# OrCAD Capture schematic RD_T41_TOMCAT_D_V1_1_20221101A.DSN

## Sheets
1 PAGE01_COVER: title: RD_T41_TOMCAT_D; rev: 1.1; note: COVER SHEET
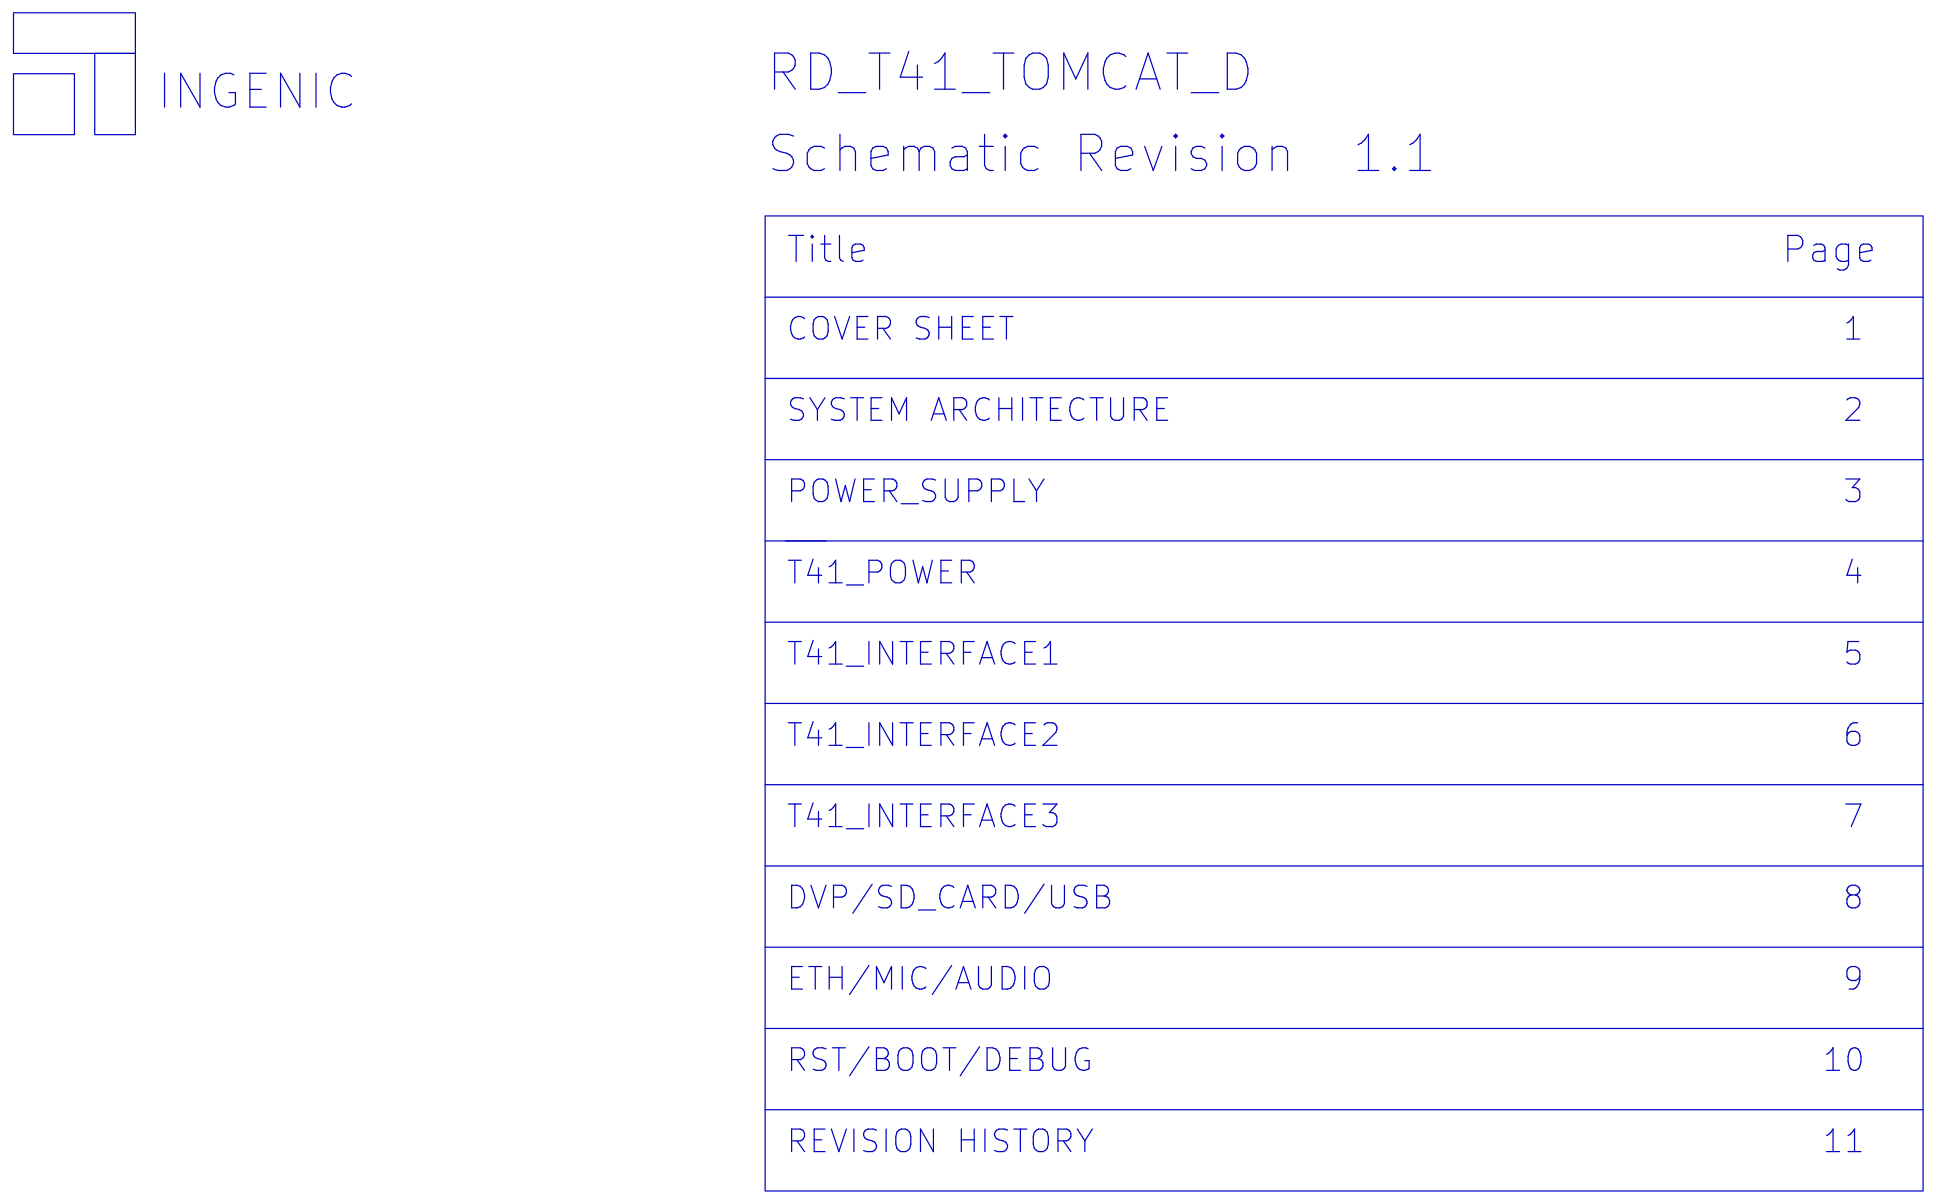
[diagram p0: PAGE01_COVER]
2 PAGE02_SYSTEM_ARCHITECT: note: SYSTEM ARCHITECTURE
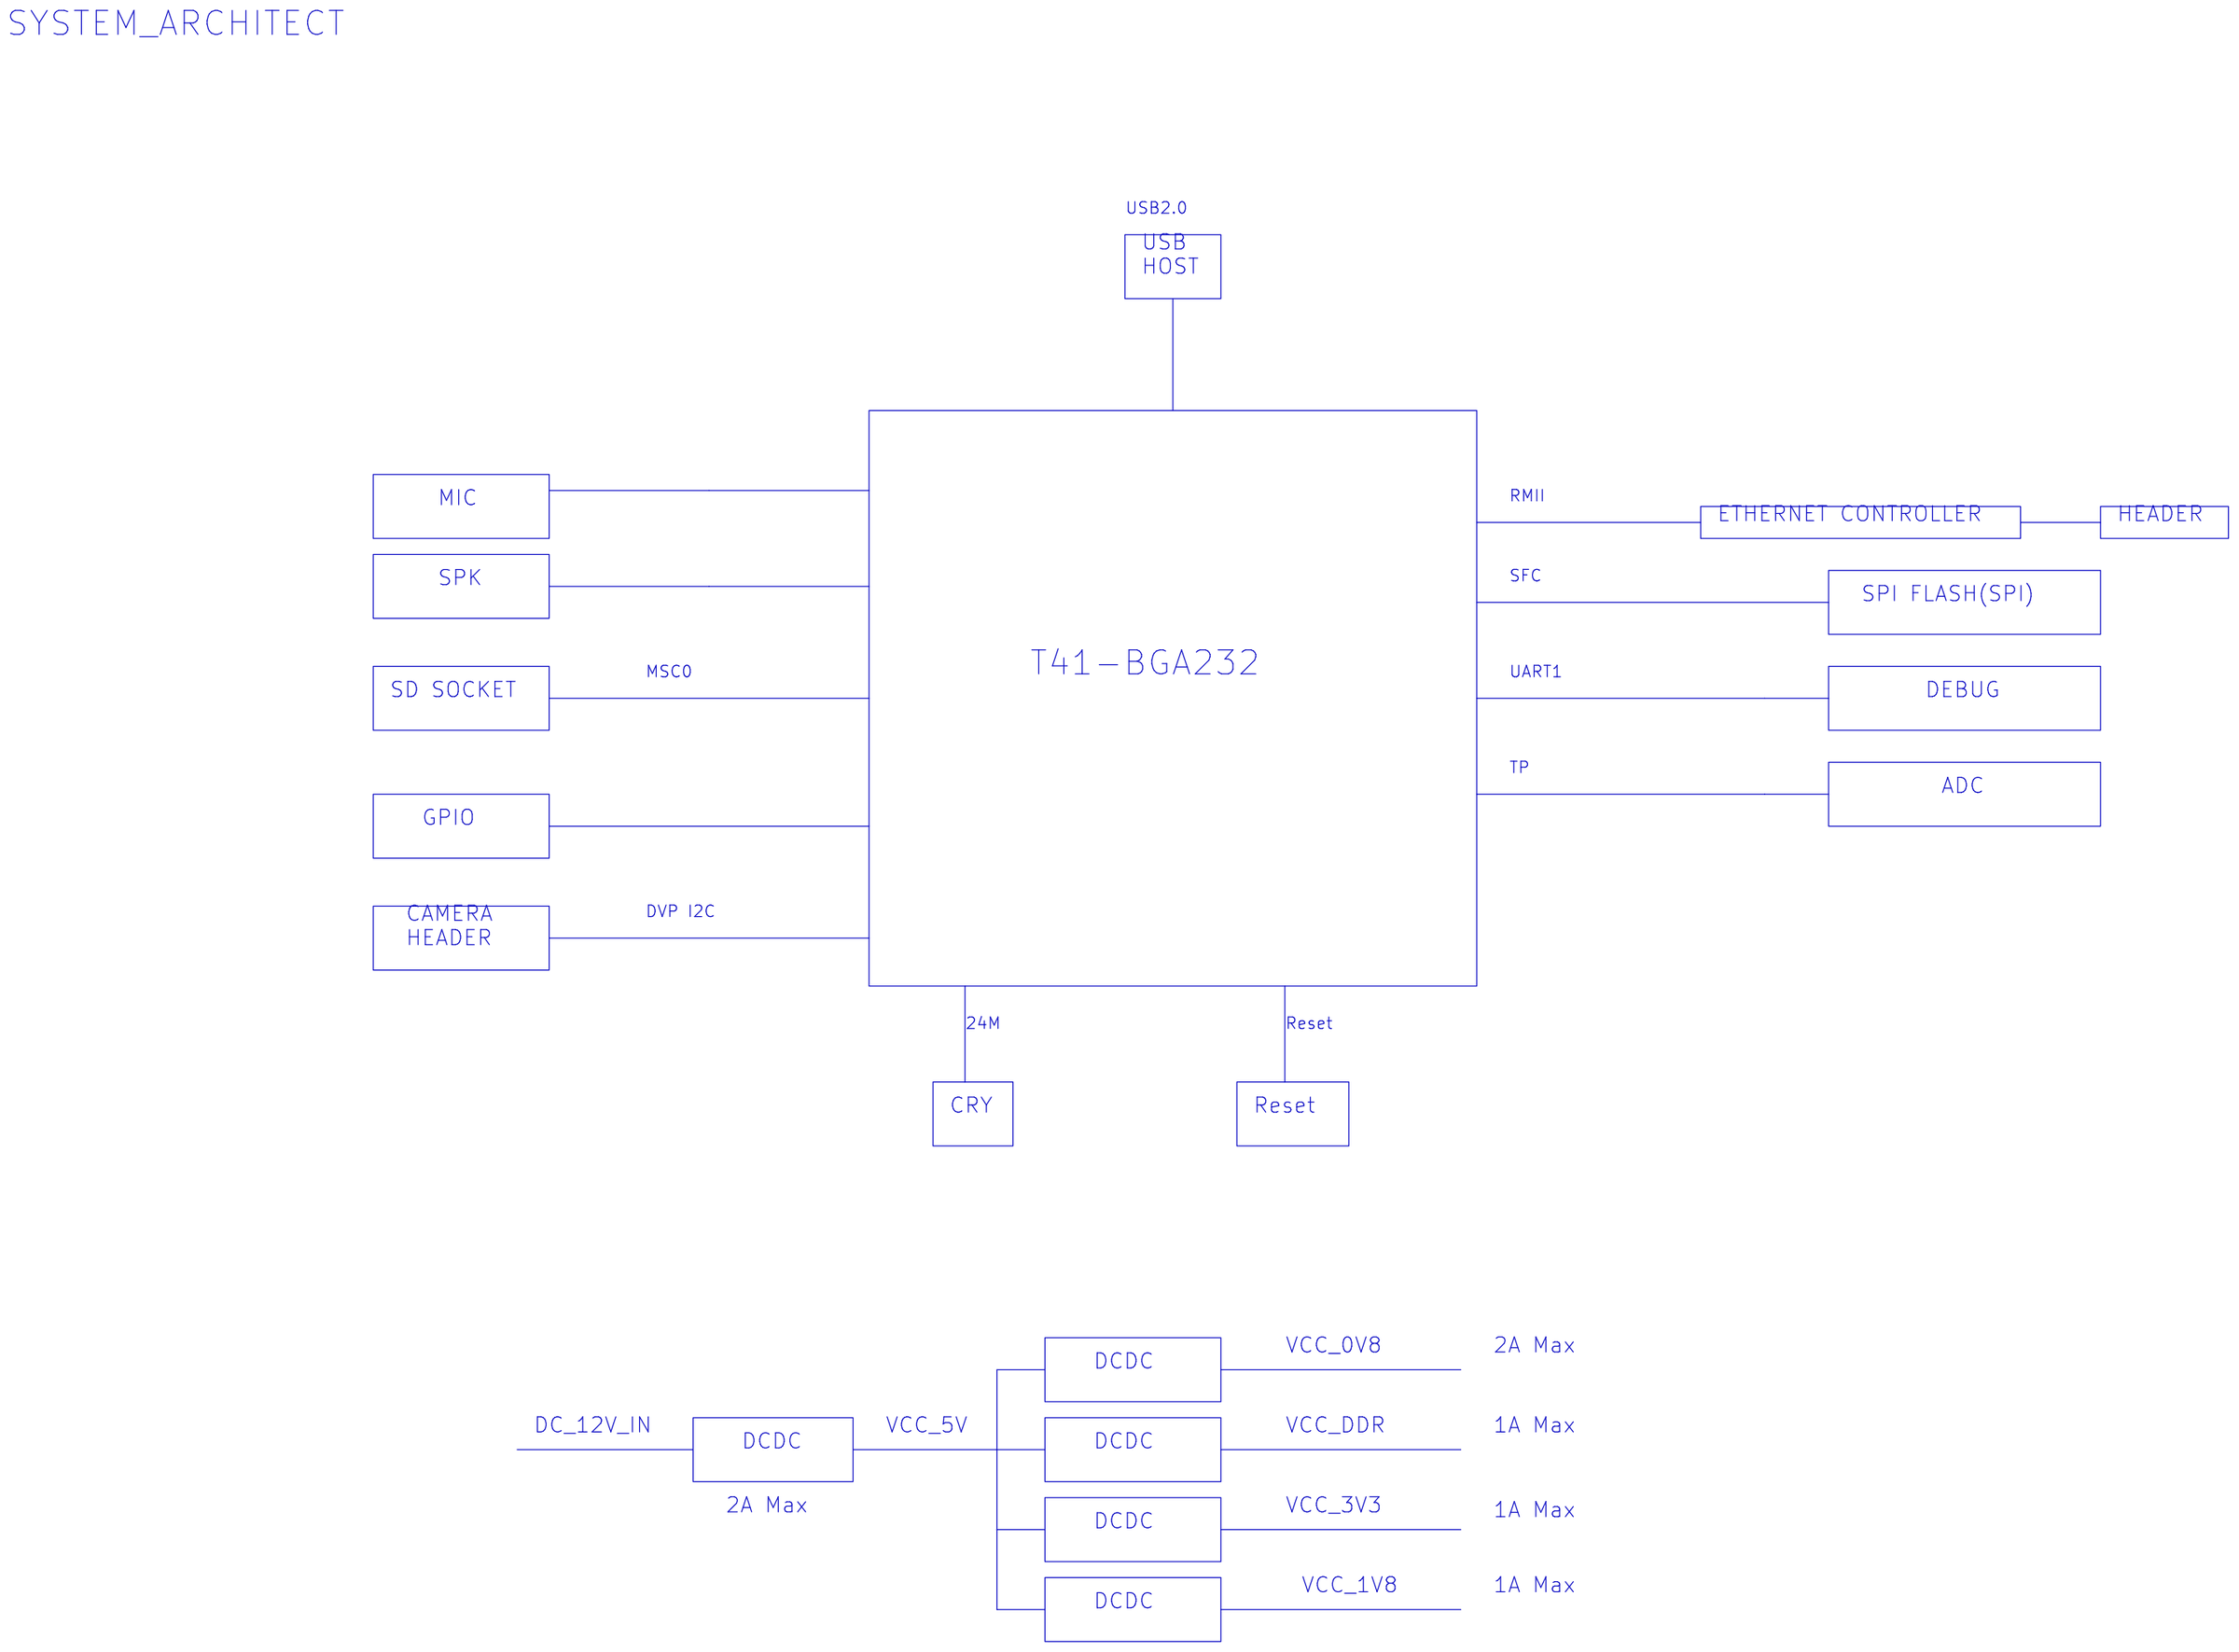
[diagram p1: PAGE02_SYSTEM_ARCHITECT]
3 PAGE03_POWER_SUPPLY: size A3; note: POWER_SUPPLY
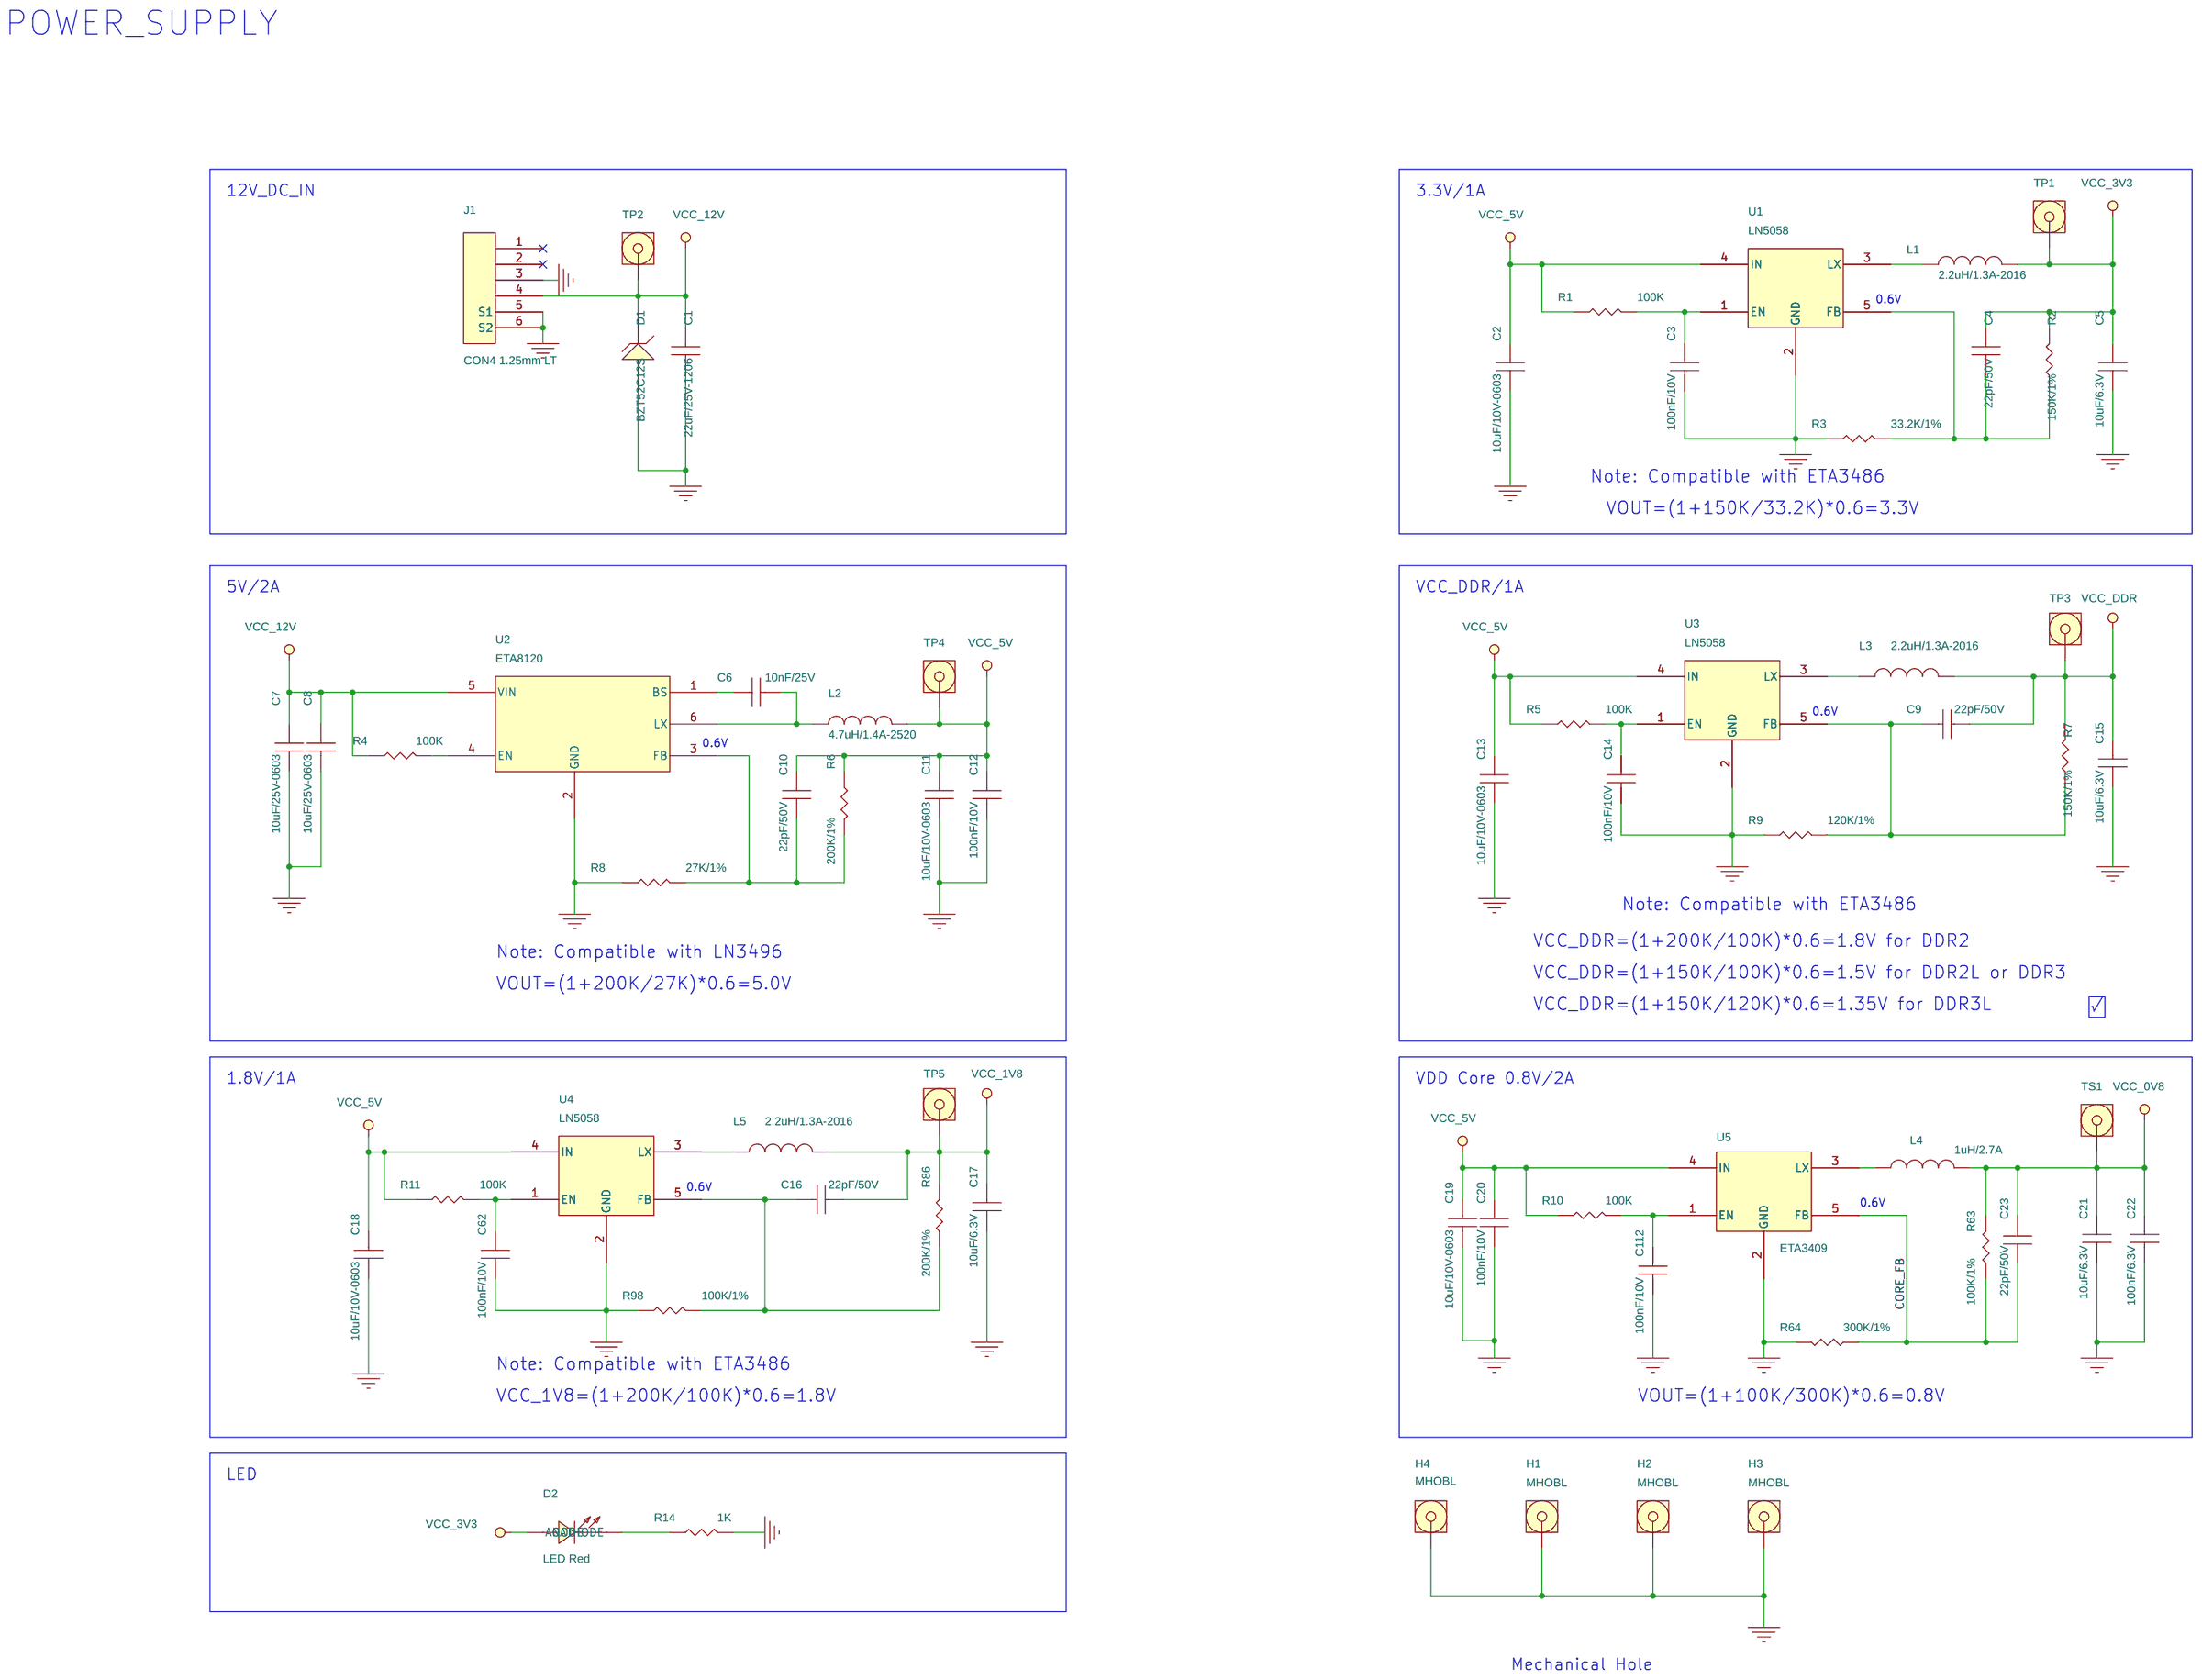
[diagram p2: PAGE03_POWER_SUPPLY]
4 PAGE04_T41_POWER: size A3; note: T41_POWER
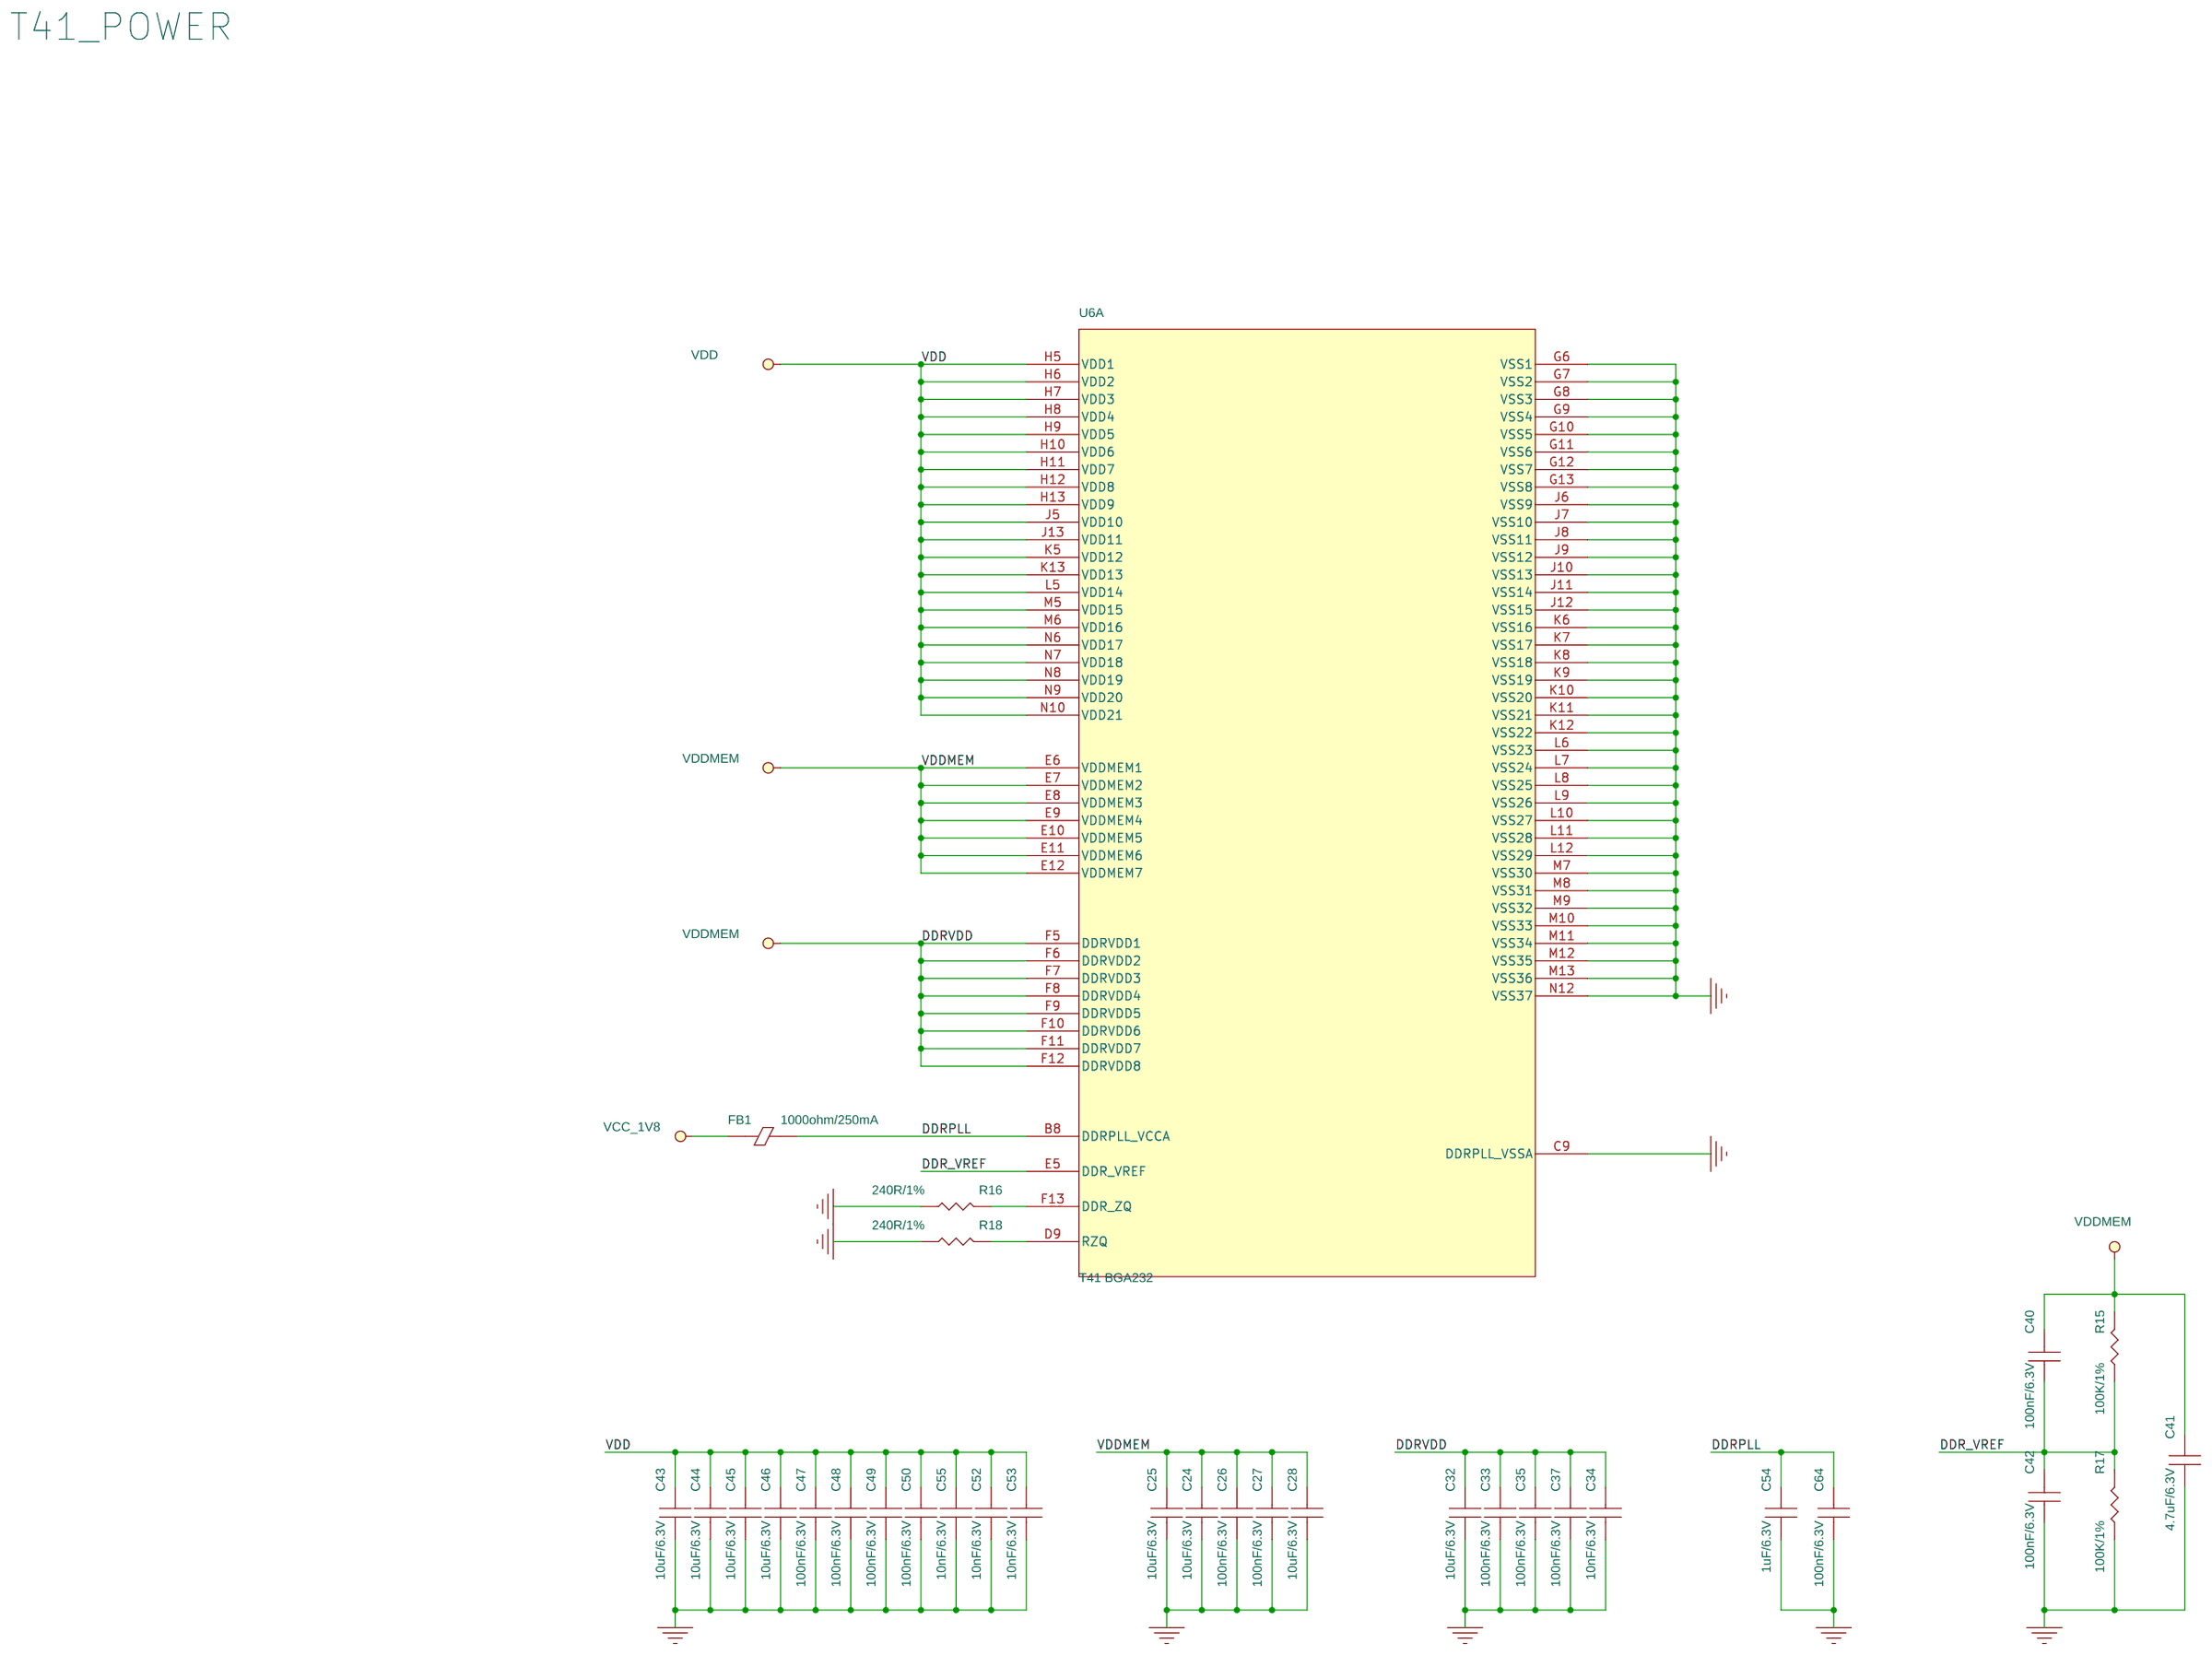
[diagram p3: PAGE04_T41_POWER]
5 PAGE05_T41_INTERFACE1: size A3; note: T41_INTERFACE1
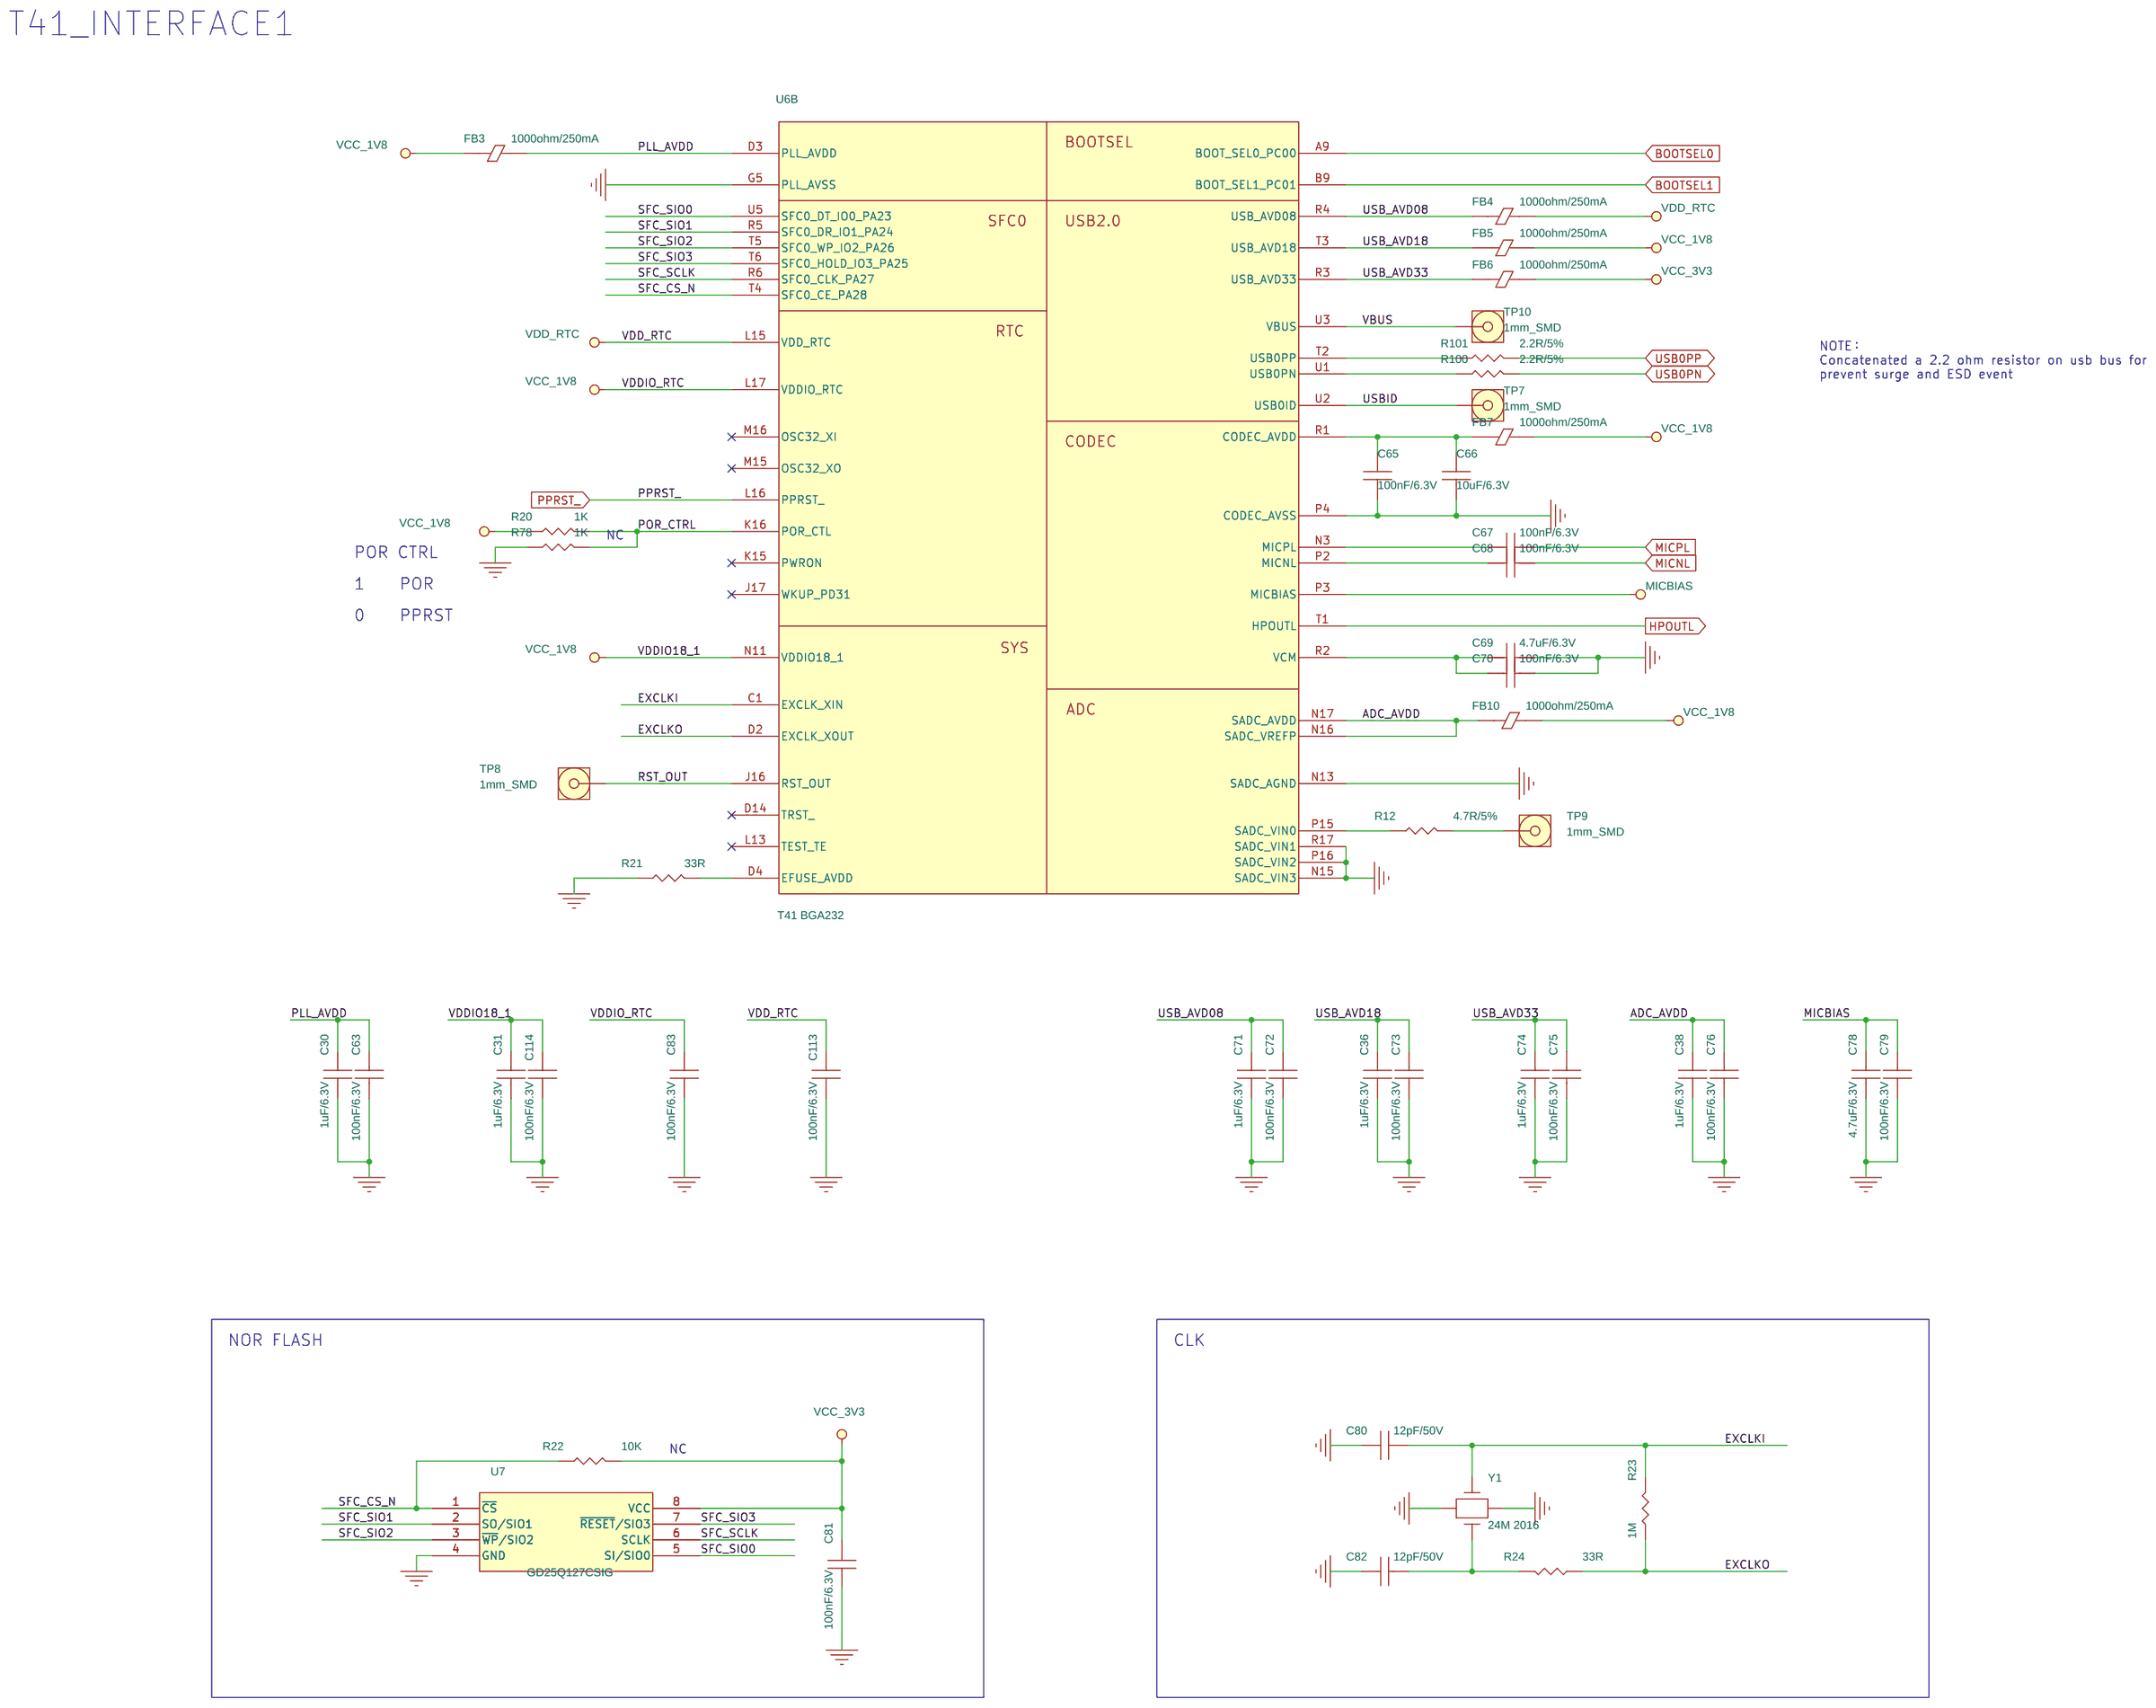
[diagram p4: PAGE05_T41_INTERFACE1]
6 PAGE06_T41_INTERFACE2: size A3; note: T41_INTERFACE2
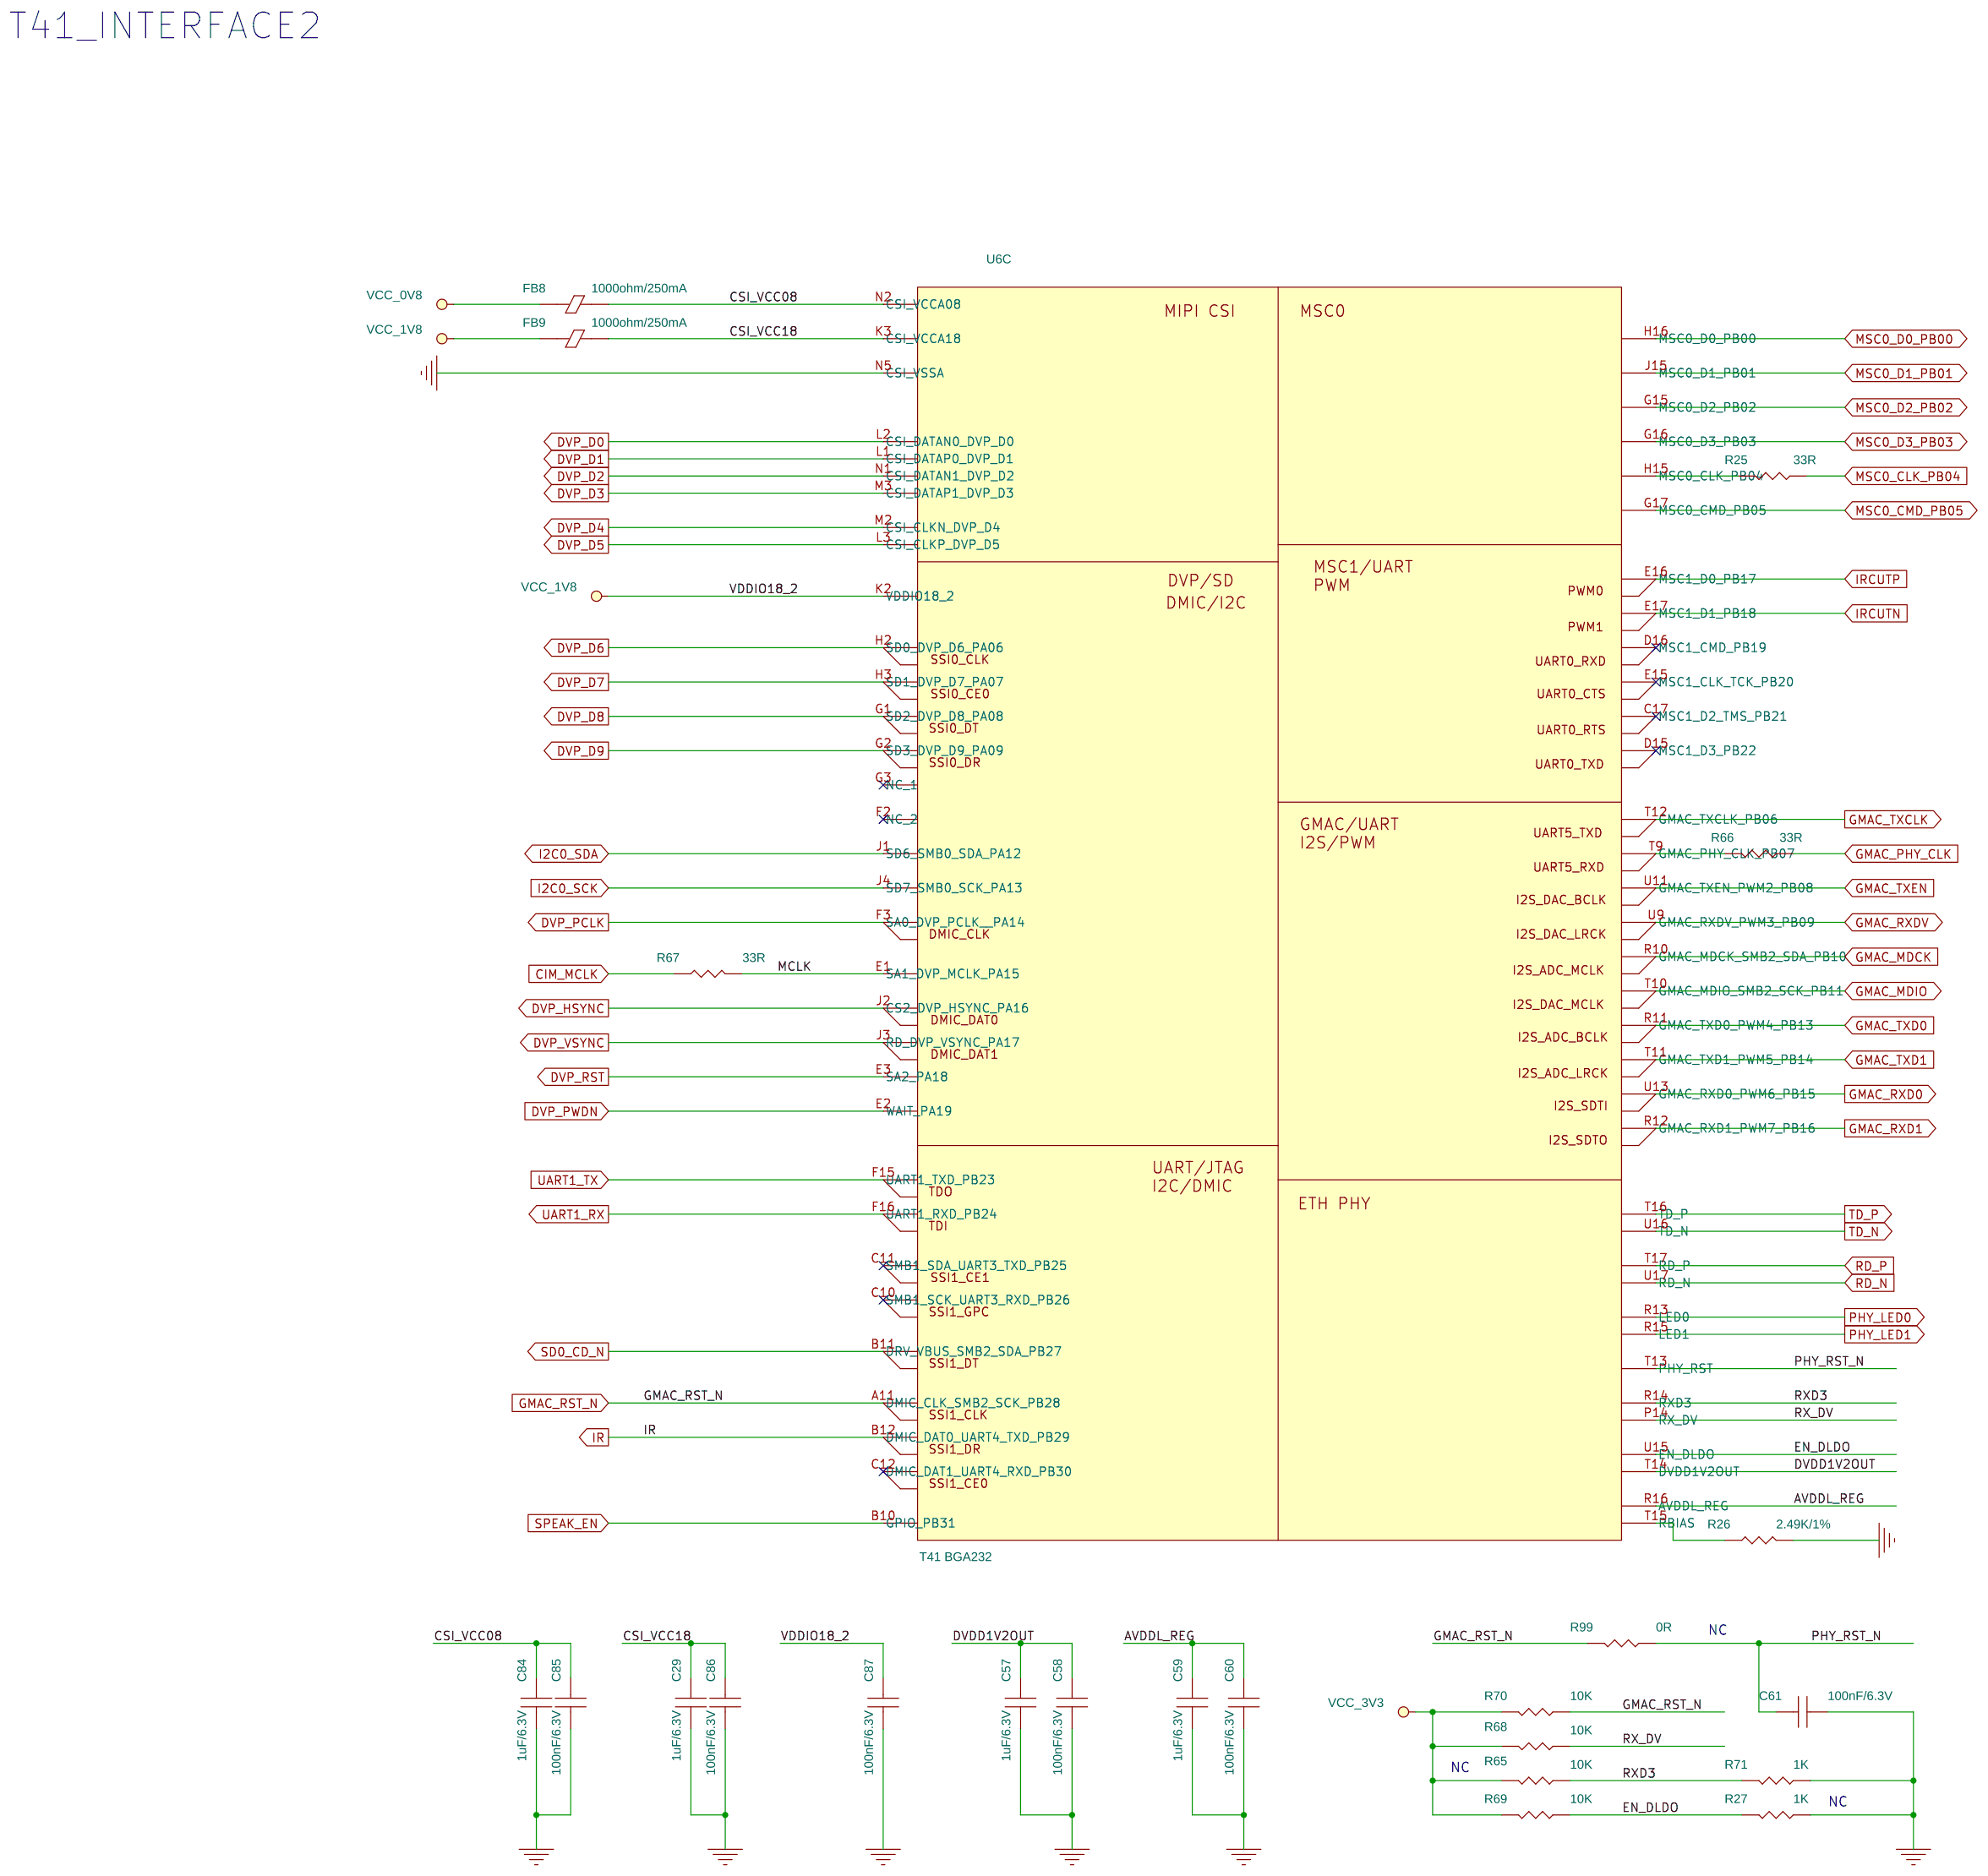
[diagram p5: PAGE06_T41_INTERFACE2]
7 PAGE07_T41_INTERFACE3: size A3; note: T41_INTERFACE3
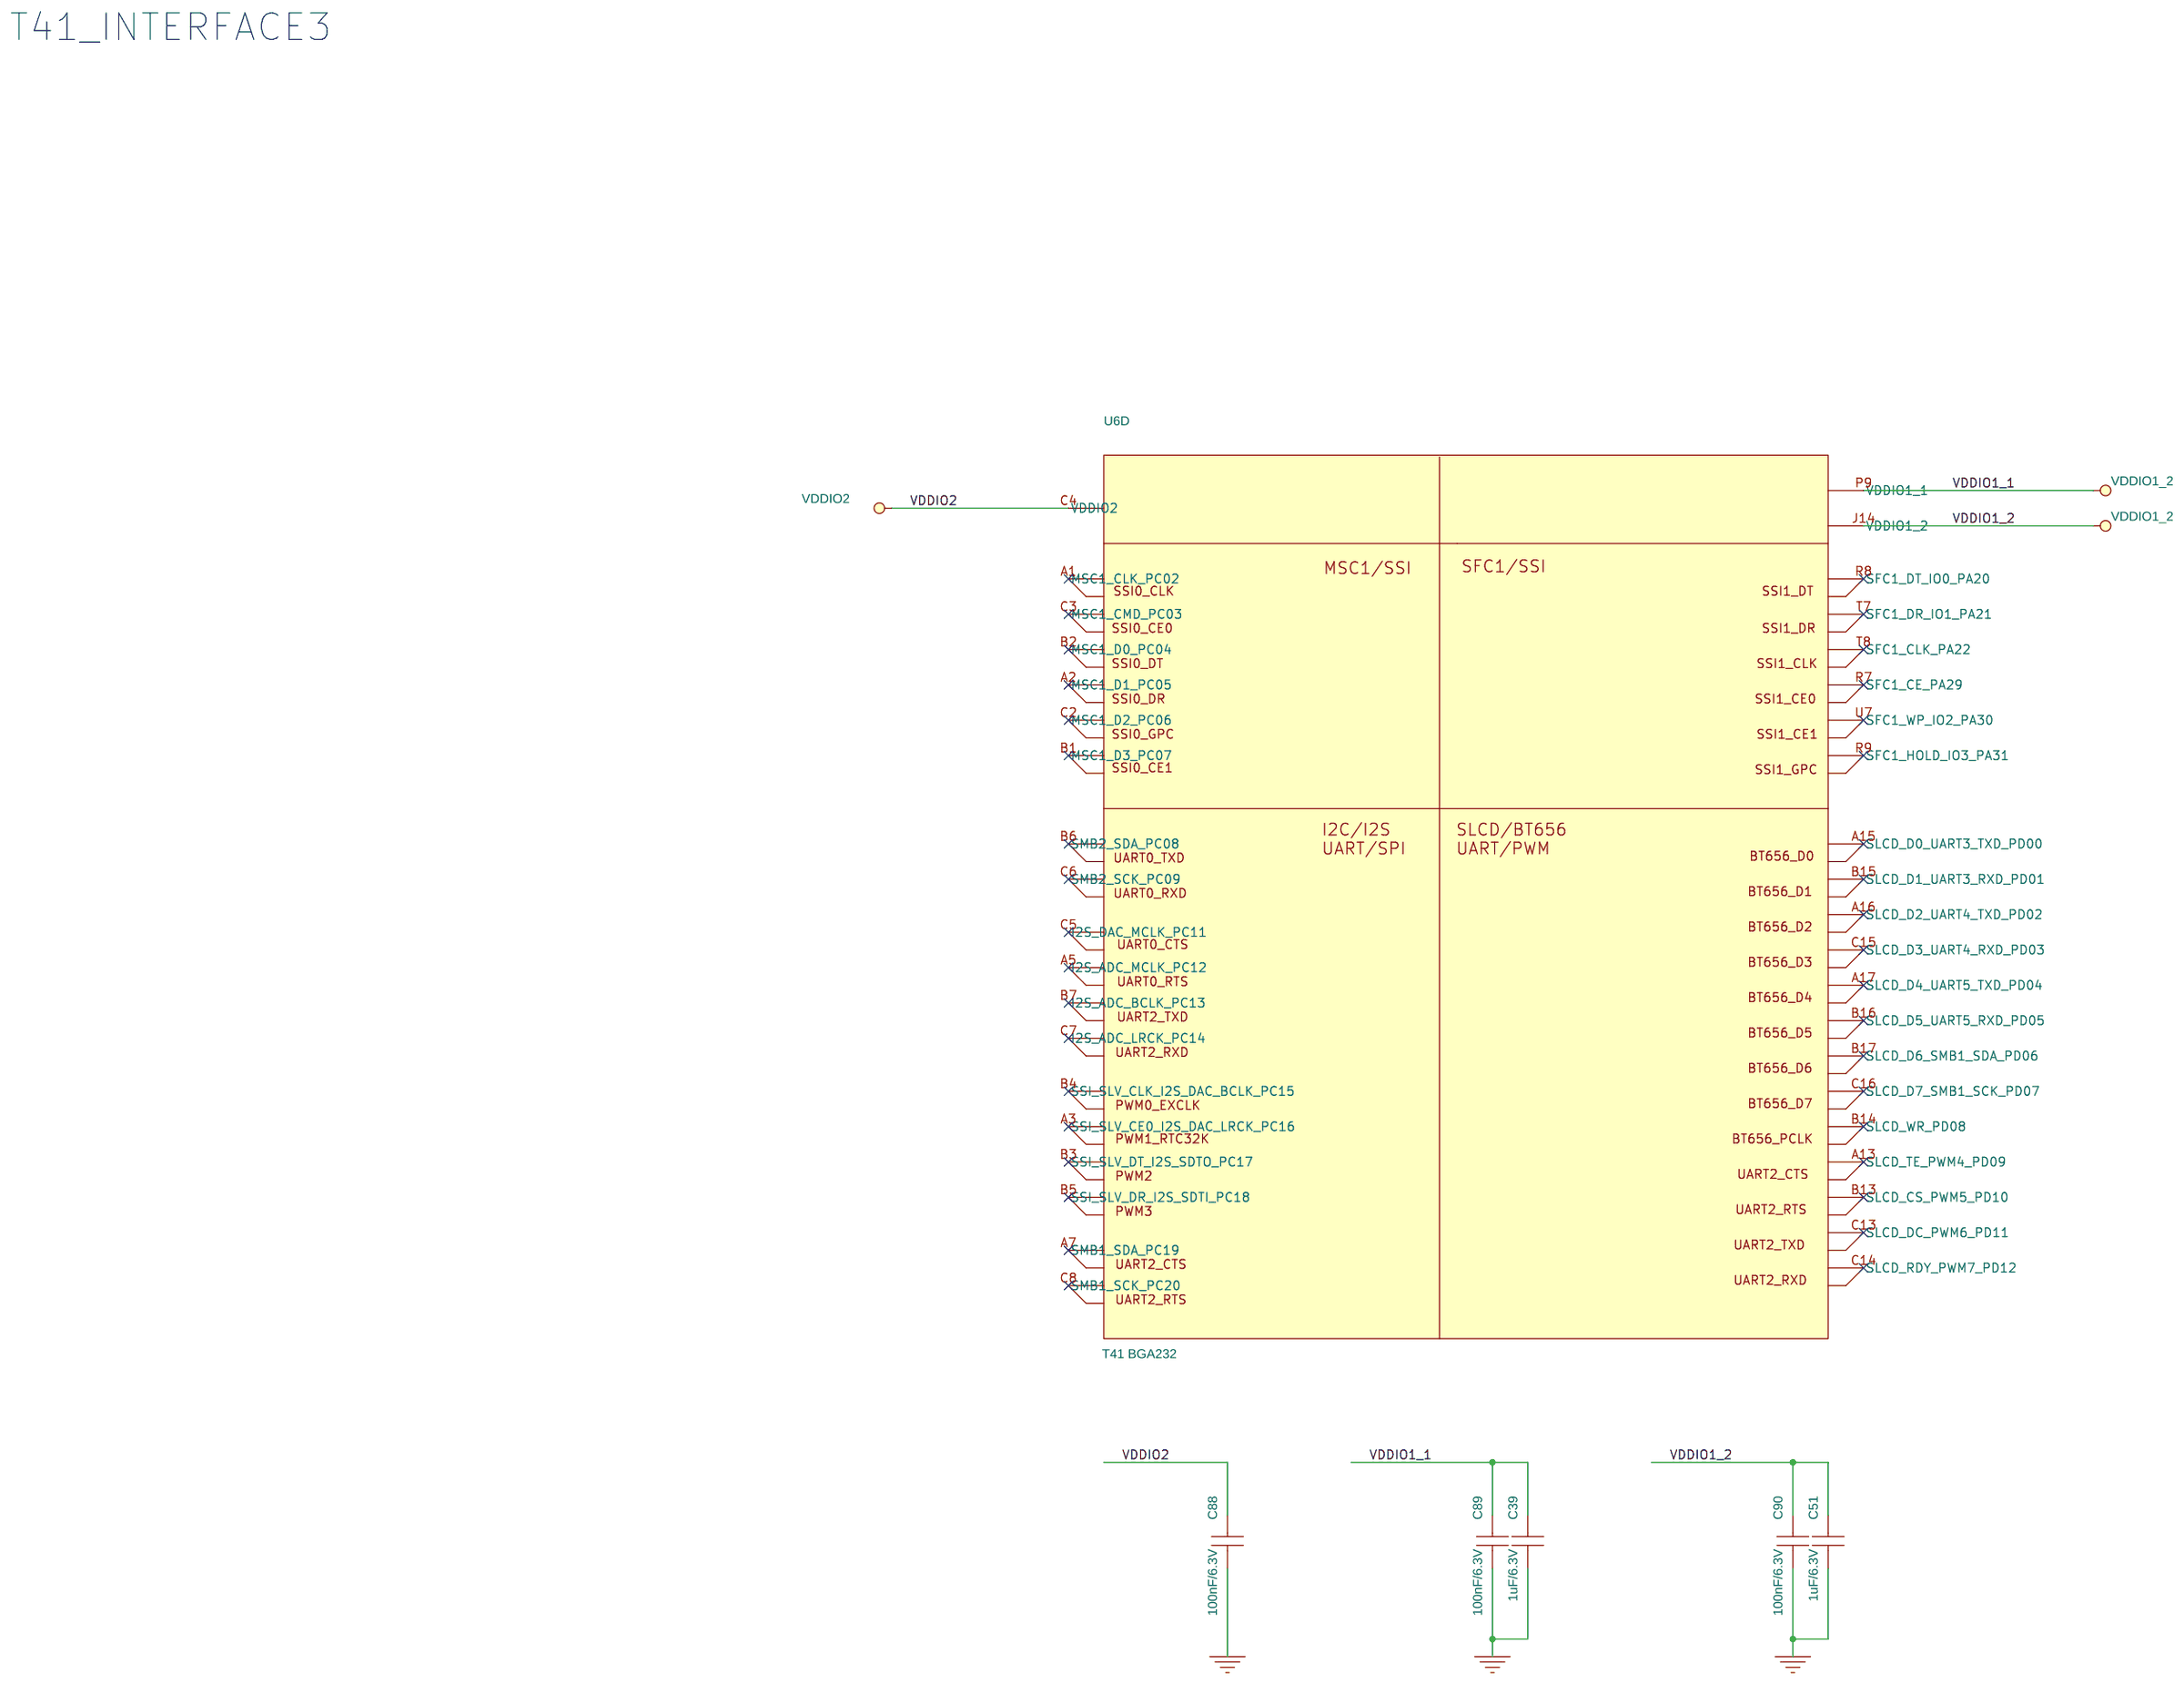
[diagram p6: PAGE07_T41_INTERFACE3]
8 PAGE11_REVISION HISTORY: note: REVISION HISTORY
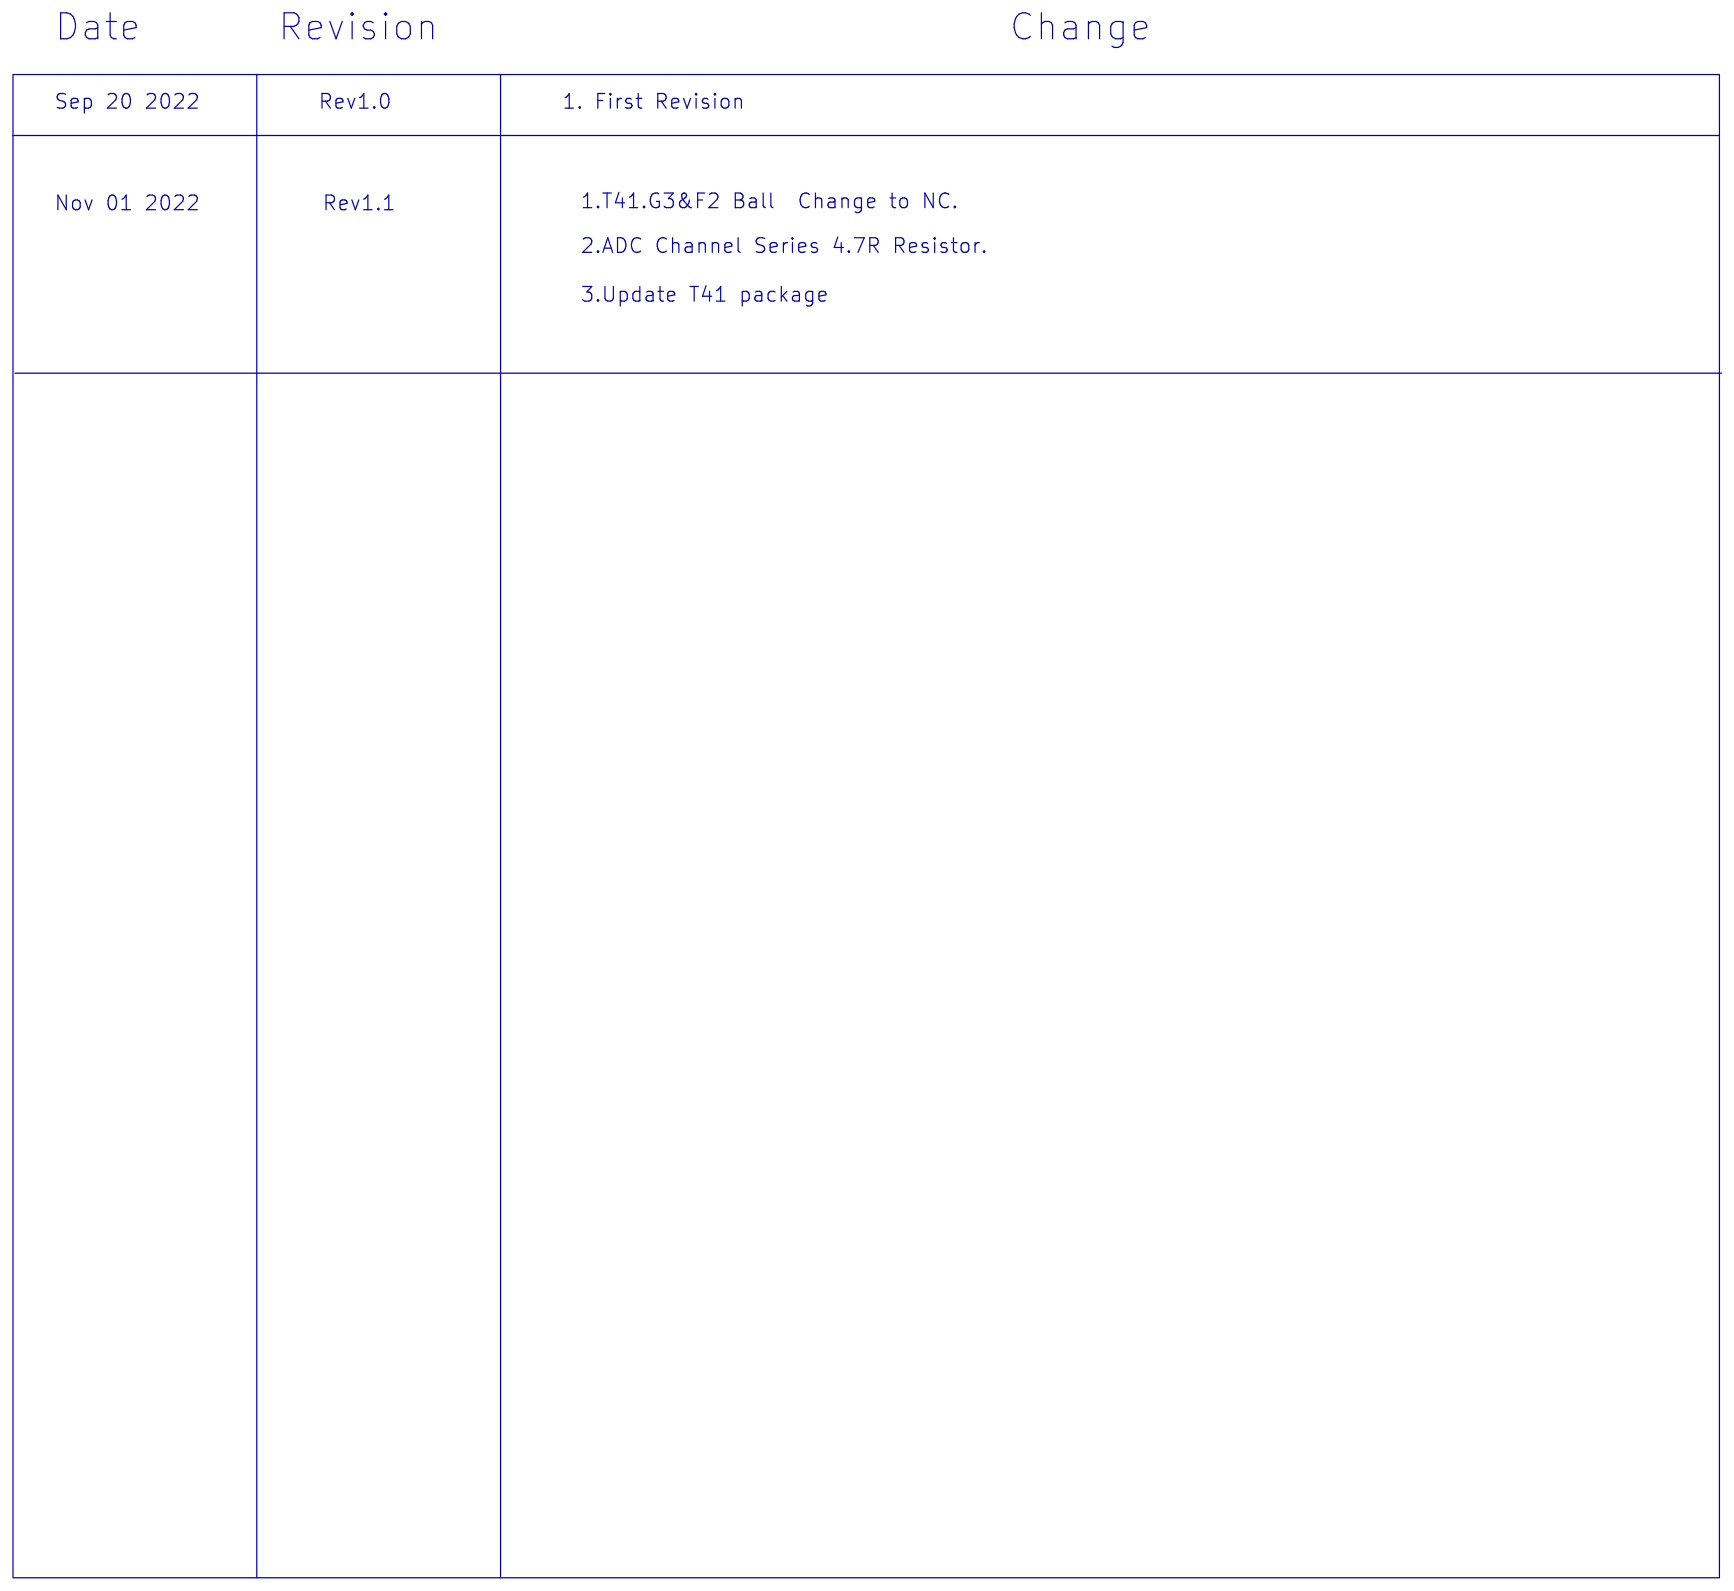
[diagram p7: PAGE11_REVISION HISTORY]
9 PAGE09_ETH/MIC/AUDIO: size A3; note: ETH/MIC/AUDIO
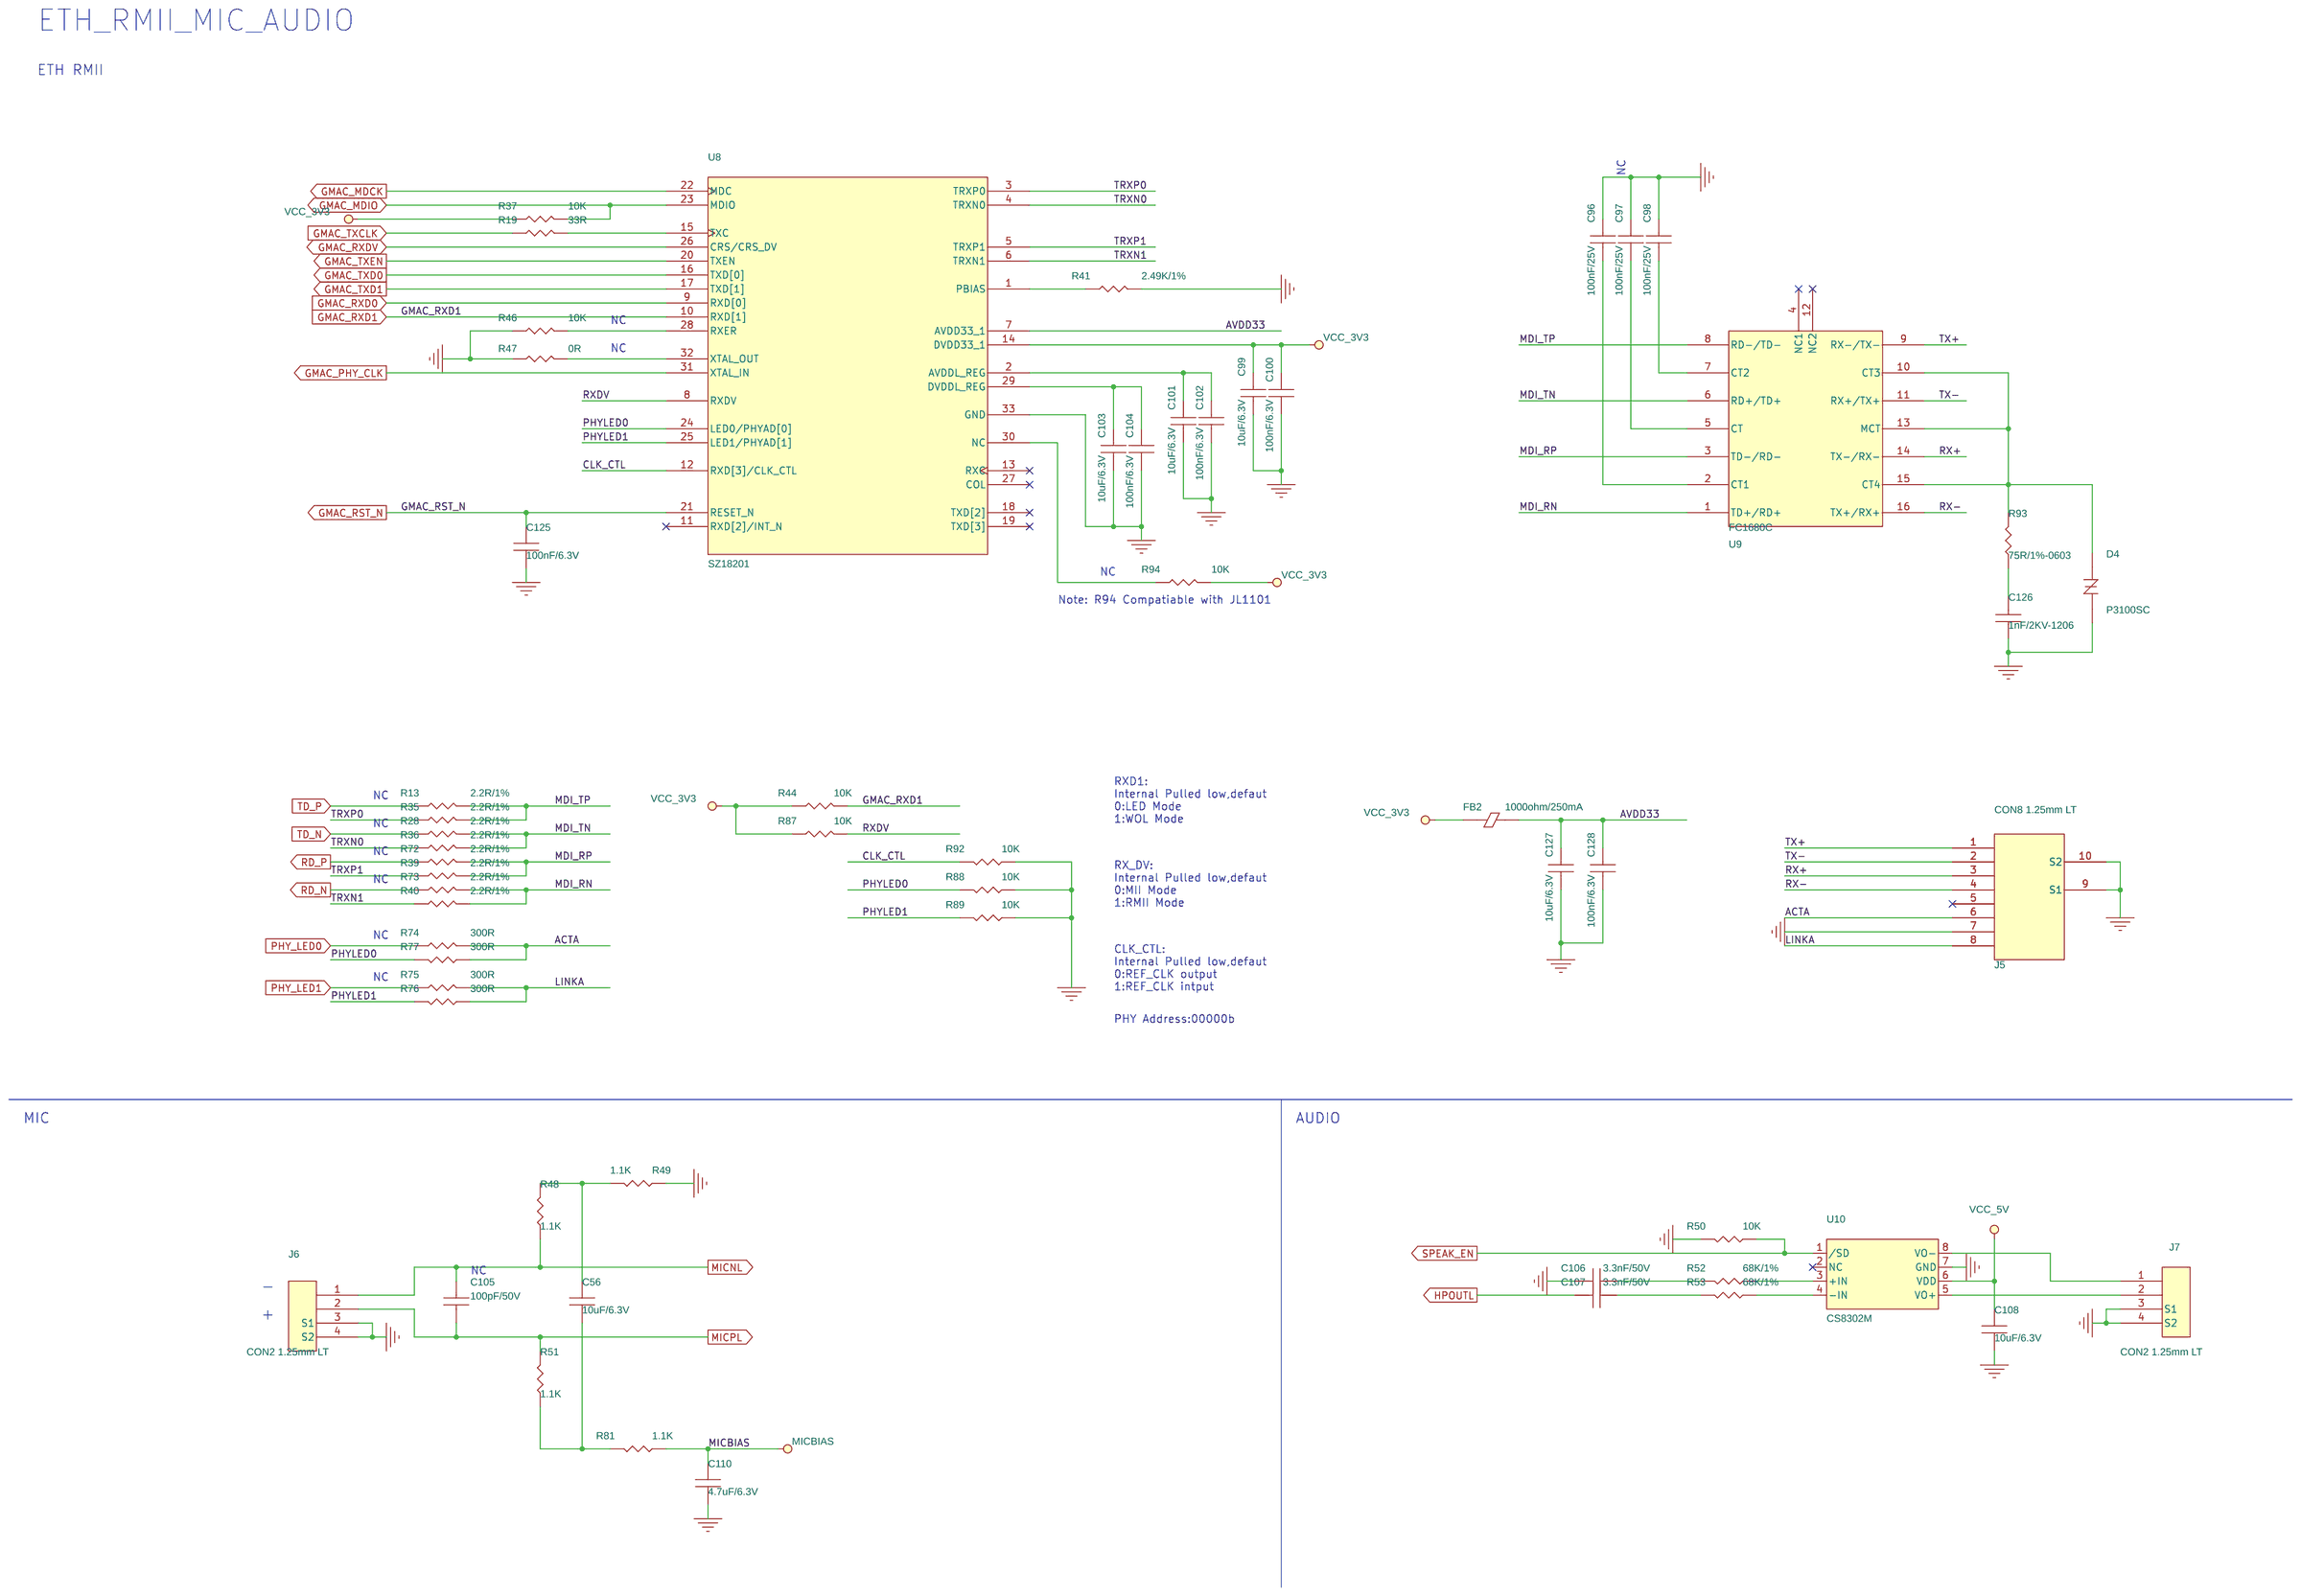
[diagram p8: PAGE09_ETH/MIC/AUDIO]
10 PAGE10_RST/BOOT/DEBUG: size A3; note: RST/BOOT/DEBUG
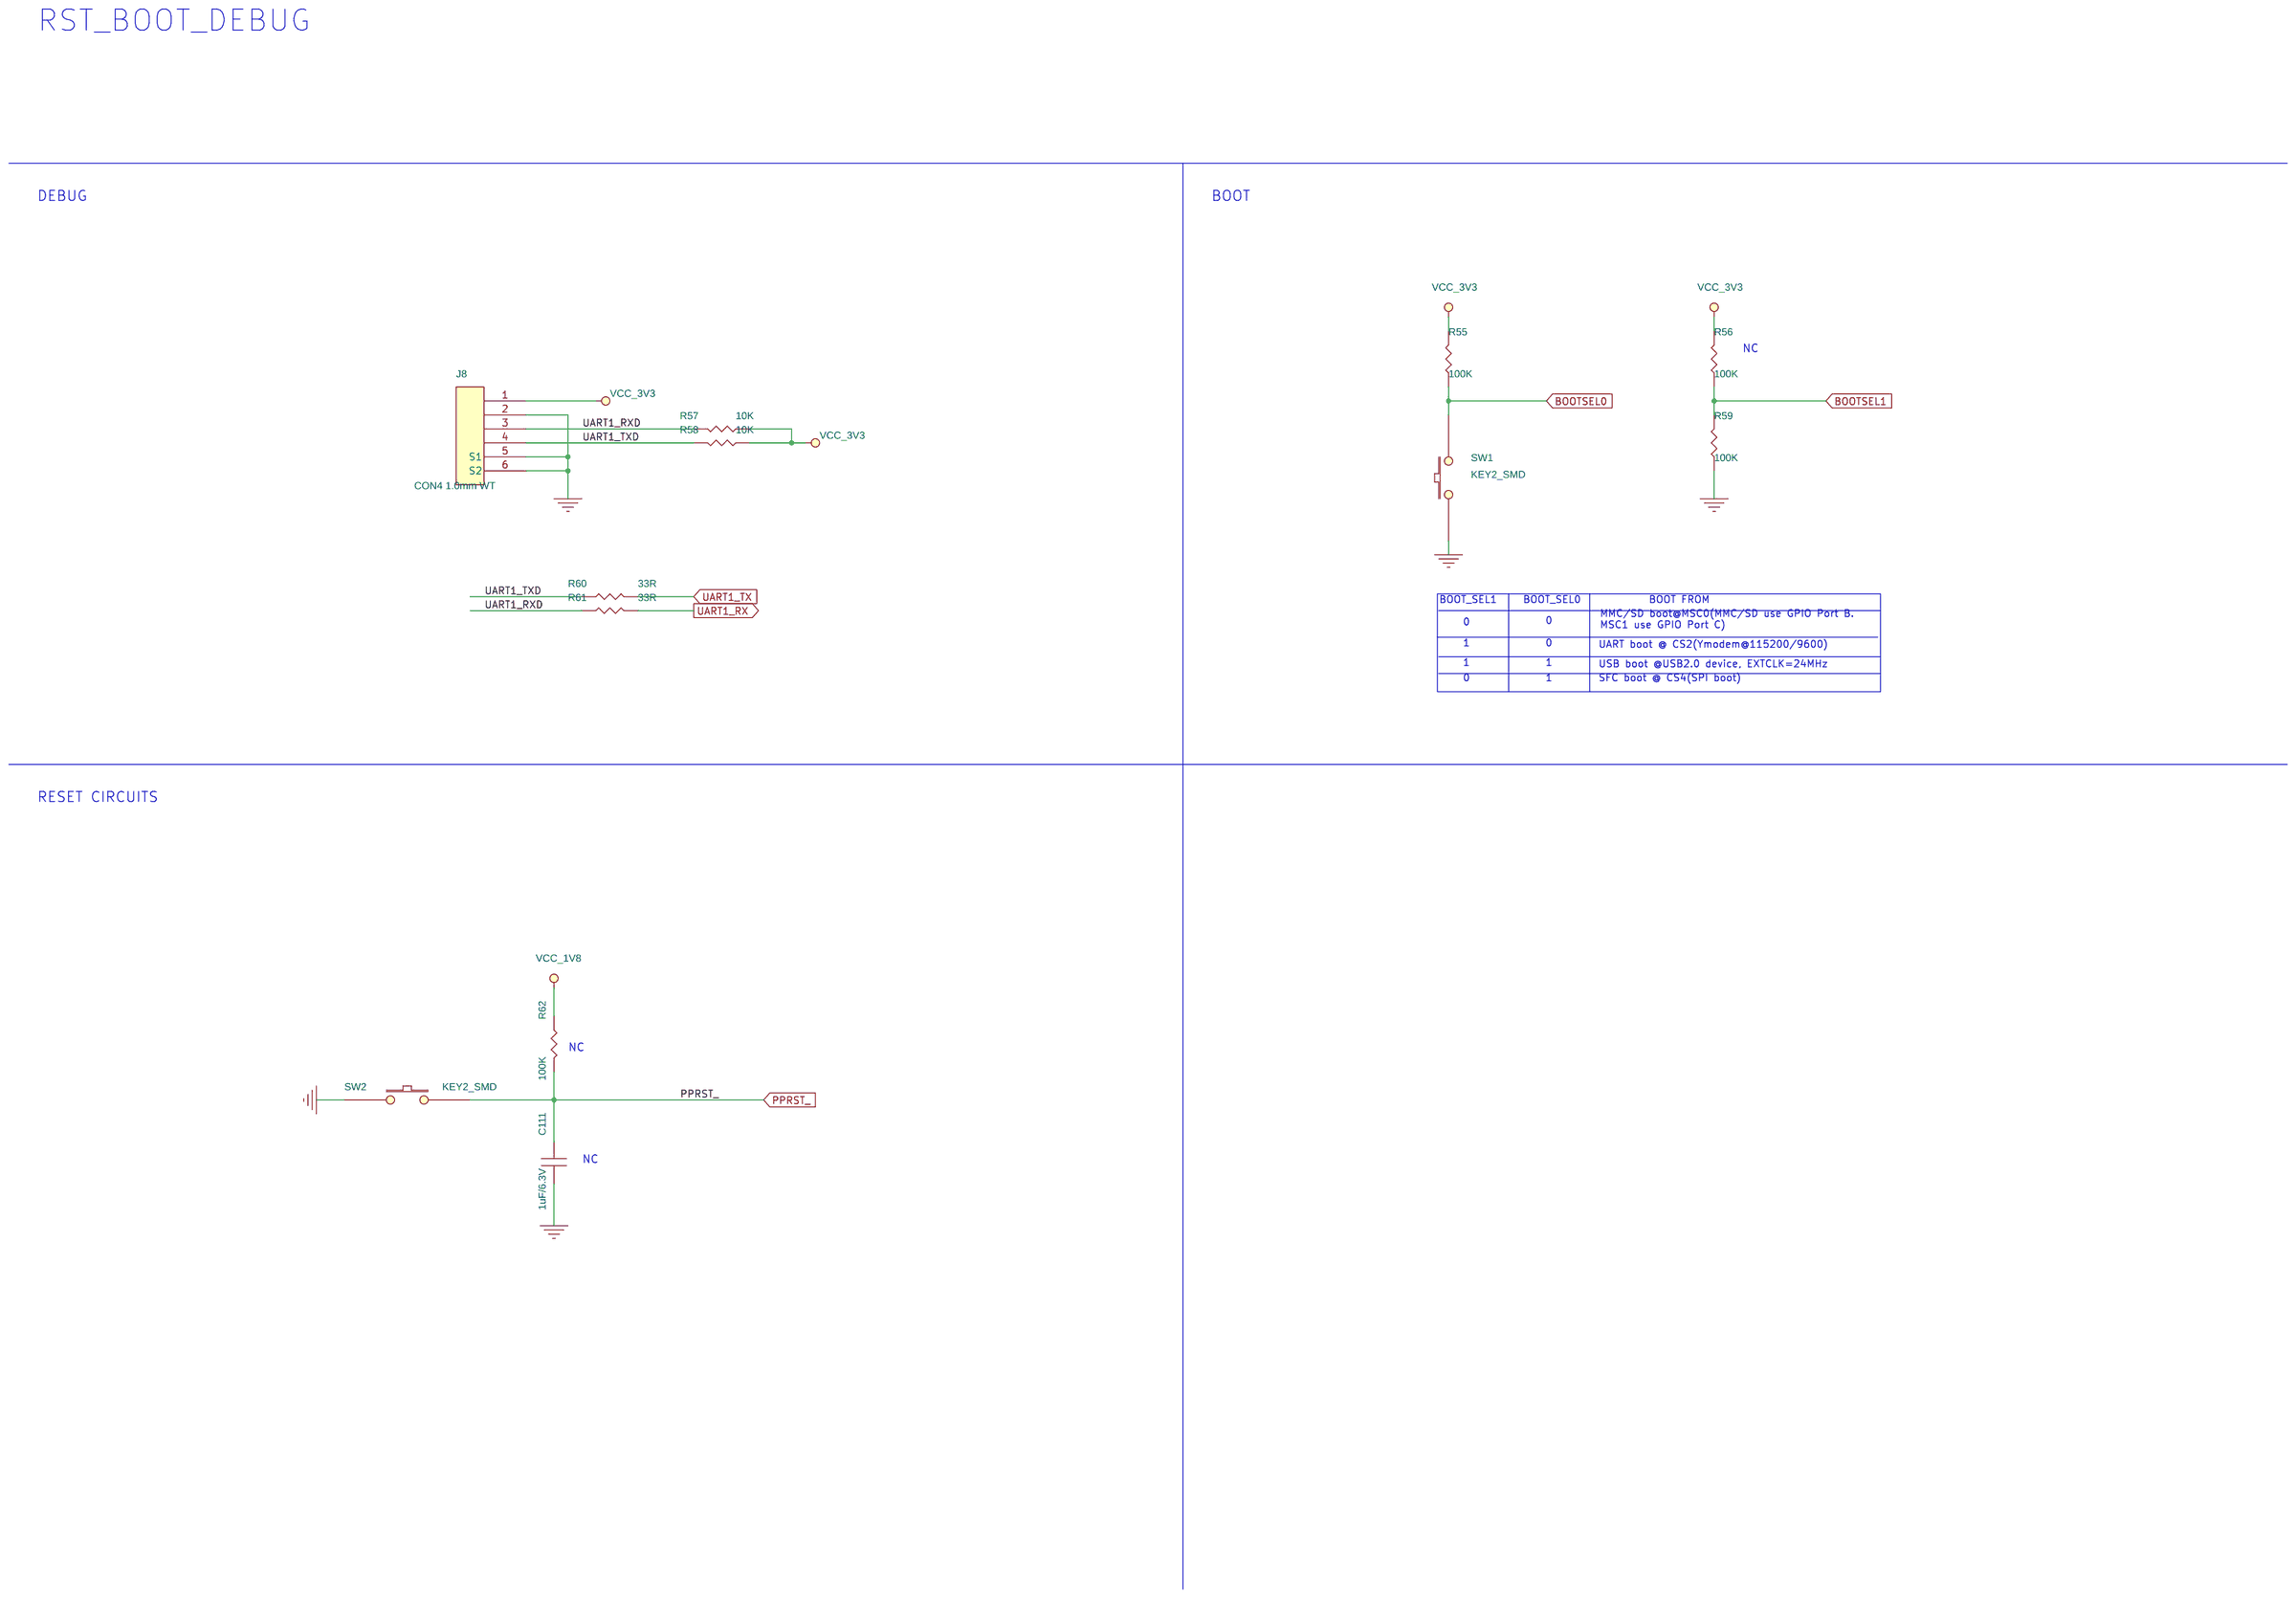
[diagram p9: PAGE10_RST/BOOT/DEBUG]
11 PAGE08_DVP/SD_CARD/USB: size A3; note: DVP/SD_CARD/USB
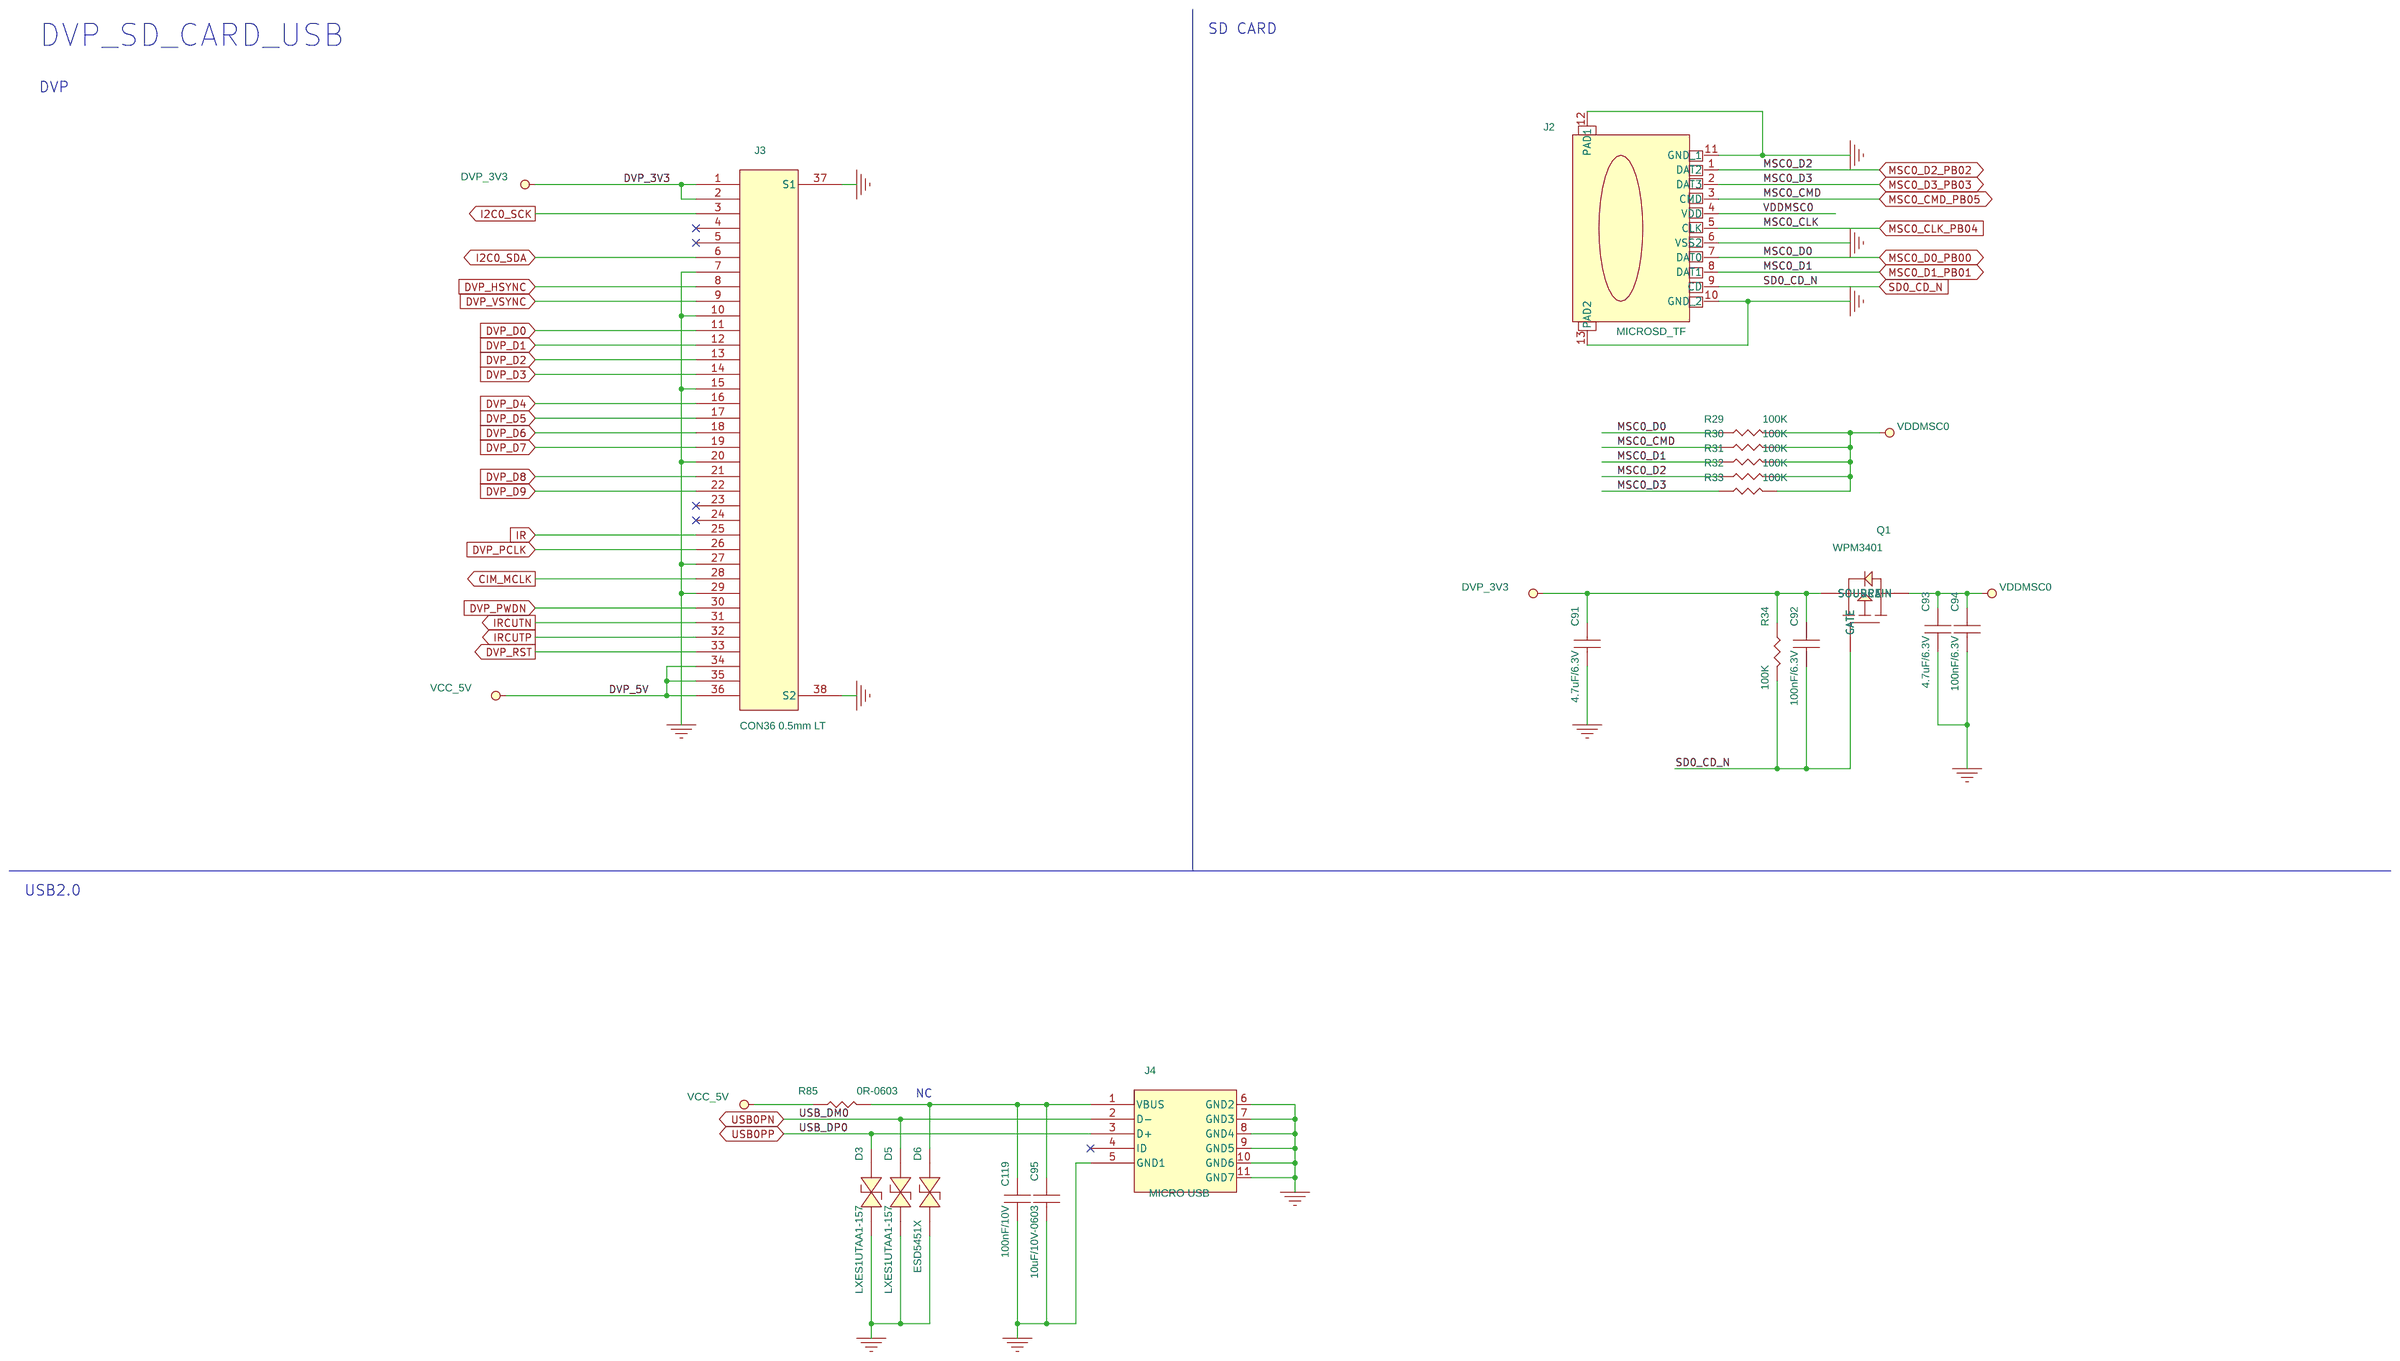
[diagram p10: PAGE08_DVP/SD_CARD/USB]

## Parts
sheet PAGE03_POWER_SUPPLY
C1  22uF/25V-1206  [C1206]
C2  10uF/10V-0603  [C0603]
C3  100nF/10V  [C0402]
C4  22pF/50V  [C0402]
C5  10uF/6.3V  [C0402_E]
C6  10nF/25V  [C0402]
C7  10uF/25V-0603  [C0603]
C8  10uF/25V-0603  [C0603]
C9  22pF/50V  [C0402]
C10  22pF/50V  [C0402]
C11  10uF/10V-0603  [C0603]
C12  100nF/10V  [C0402]
C13  10uF/10V-0603  [C0603]
C14  100nF/10V  [C0402]
C15  10uF/6.3V  [C0402_E]
C16  22pF/50V  [C0402]
C17  10uF/6.3V  [C0402_E]
C18  10uF/10V-0603  [C0603]
C19  10uF/10V-0603  [C0603]
C20  100nF/10V  [C0402]
C21  10uF/6.3V  [C0402_E]
C22  100nF/6.3V  [C0402]
C23  22pF/50V  [C0402]
C62  100nF/10V  [C0402]
C112  100nF/10V  [C0402]
D1  BZT52C12S  [SOD323]
D2  LED Red  [D0603_LED]
H1  MHOBL  [MHOLE_3D0X2D0]
H2  MHOBL  [MHOLE_3D0X2D0]
H3  MHOBL  [MHOLE_3D0X2D0]
H4  MHOBL  [MHOLE_3D0X2D0]
J1  CON4 1.25mm LT  [CON4-1D25-LT]
L1  2.2uH/1.3A-2016  [L2016]
L2  4.7uH/1.4A-2520  [L2520]
L3  2.2uH/1.3A-2016  [L2016]
L4  1uH/2.7A  [L2016]
L5  2.2uH/1.3A-2016  [L2016]
R1  100K  [R0402]
R2  150K/1%  [R0402]
R3  33.2K/1%  [R0402]
R4  100K  [R0402]
R5  100K  [R0402]
R6  200K/1%  [R0402]
R7  150K/1%  [R0402]
R8  27K/1%  [R0402]
R9  120K/1%  [R0402]
R10  100K  [R0402]
R11  100K  [R0402]
R14  1K  [R0402]
R63  100K/1%  [R0402]
R64  300K/1%  [R0402]
R86  200K/1%  [R0402]
R98  100K/1%  [R0402]
TP1  1mm_SMD  [TEST_SMD]
TP2  1mm_SMD  [TEST_SMD]
TP3  1mm_SMD  [TEST_SMD]
TP4  1mm_SMD  [TEST_SMD]
TP5  1mm_SMD  [TEST_SMD]
TS1  1mm_SMD  [TEST_SMD]
U1  LN5058  [SOT23-5]
U2  ETA8120  [SOT23-6]
U3  LN5058  [SOT23-5]
U4  LN5058  [SOT23-5]
U5  ETA3409  [SOT23-5]
sheet PAGE04_T41_POWER
C24  10uF/6.3V  [C0402_E]
C25  10uF/6.3V  [C0402_E]
C26  100nF/6.3V  [C0402]
C27  100nF/6.3V  [C0402]
C28  10uF/6.3V  [C0402_E]
C32  10uF/6.3V  [C0402_E]
C33  100nF/6.3V  [C0402]
C34  10nF/6.3V  [C0402]
C35  100nF/6.3V  [C0402]
C37  100nF/6.3V  [C0402]
C40  100nF/6.3V  [C0402]
C41  4.7uF/6.3V  [C0402]
C42  100nF/6.3V  [C0402]
C43  10uF/6.3V  [C0402_E]
C44  10uF/6.3V  [C0402_E]
C45  10uF/6.3V  [C0402_E]
C46  10uF/6.3V  [C0402_E]
C47  100nF/6.3V  [C0402]
C48  100nF/6.3V  [C0402]
C49  100nF/6.3V  [C0402]
C50  100nF/6.3V  [C0402]
C52  10nF/6.3V  [C0402]
C53  10nF/6.3V  [C0402]
C54  1uF/6.3V  [C0402]
C55  10nF/6.3V  [C0402]
C64  100nF/6.3V  [C0402]
FB1  1000ohm/250mA  [FB0402]
R15  100K/1%  [R0402]
R16  240R/1%  [R0402]
R17  100K/1%  [R0402]
R18  240R/1%  [R0402]
sheet PAGE05_T41_INTERFACE1
C30  1uF/6.3V  [C0402]
C31  1uF/6.3V  [C0402]
C36  1uF/6.3V  [C0402]
C38  1uF/6.3V  [C0402]
C63  100nF/6.3V  [C0402]
C65  100nF/6.3V  [C0402]
C66  10uF/6.3V  [C0402_E]
C67  100nF/6.3V  [C0402]
C68  100nF/6.3V  [C0402]
C69  4.7uF/6.3V  [C0402]
C70  100nF/6.3V  [C0402]
C71  1uF/6.3V  [C0402]
C72  100nF/6.3V  [C0402]
C73  100nF/6.3V  [C0402]
C74  1uF/6.3V  [C0402]
C75  100nF/6.3V  [C0402]
C76  100nF/6.3V  [C0402]
C78  4.7uF/6.3V  [C0402]
C79  100nF/6.3V  [C0402]
C80  12pF/50V  [C0402]
C81  100nF/6.3V  [C0402]
C82  12pF/50V  [C0402]
C83  100nF/6.3V  [C0402]
C113  100nF/6.3V  [C0402]
C114  100nF/6.3V  [C0402]
FB3  1000ohm/250mA  [FB0402]
FB4  1000ohm/250mA  [FB0402]
FB5  1000ohm/250mA  [FB0402]
FB6  1000ohm/250mA  [FB0402]
FB7  1000ohm/250mA  [FB0402]
FB10  1000ohm/250mA  [FB0402]
R12  4.7R/5%  [R0402]
R20  1K  [R0402]
R21  33R  [R0402]
R22  10K  [R0402]
R23  1M  [R0402]
R24  33R  [R0402]
R78  1K  [R0402]
R100  2.2R/5%  [R0402]
R101  2.2R/5%  [R0402]
TP7  1mm_SMD  [TEST_SMD]
TP8  1mm_SMD  [TEST_SMD]
TP9  1mm_SMD  [TEST_SMD]
TP10  1mm_SMD  [TEST_SMD]
U6  T41 BGA232  [BGA232_0D65_T41]  (sections A,B,C,D)
U7  GD25Q127CSIG  [WSOP8_1D27]
Y1  24M 2016  [CRY_2D5X2D0]
sheet PAGE06_T41_INTERFACE2
C29  1uF/6.3V  [C0402]
C57  1uF/6.3V  [C0402]
C58  100nF/6.3V  [C0402]
C59  1uF/6.3V  [C0402]
C60  100nF/6.3V  [C0402]
C61  100nF/6.3V  [C0402]
C84  1uF/6.3V  [C0402]
C85  100nF/6.3V  [C0402]
C86  100nF/6.3V  [C0402]
C87  100nF/6.3V  [C0402]
FB8  1000ohm/250mA  [FB0402]
FB9  1000ohm/250mA  [FB0402]
R25  33R  [R0402]
R26  2.49K/1%  [R0402]
R27  1K  [R0402]
R65  10K  [R0402]
R66  33R  [R0402]
R67  33R  [R0402]
R68  10K  [R0402]
R69  10K  [R0402]
R70  10K  [R0402]
R71  1K  [R0402]
R99  0R  [R0402]
sheet PAGE07_T41_INTERFACE3
C39  1uF/6.3V  [C0402]
C51  1uF/6.3V  [C0402]
C88  100nF/6.3V  [C0402]
C89  100nF/6.3V  [C0402]
C90  100nF/6.3V  [C0402]
sheet PAGE08_DVP/SD_CARD/USB
C91  4.7uF/6.3V  [C0402]
C92  100nF/6.3V  [C0402]
C93  4.7uF/6.3V  [C0402]
C94  100nF/6.3V  [C0402]
C95  10uF/10V-0603  [C0603]
C119  100nF/10V  [C0402]
D3  LXES1UTAA1-157  [DFN1006]
D5  LXES1UTAA1-157  [DFN1006]
D6  ESD5451X  [ESD0402]
J2  MICROSD_TF  [TFCARD]
J3  CON36 0.5mm LT  [FPC-CON36-0D5-LT]
J4  MICRO USB  [MICROUSB_B_NJ5P]
Q1  WPM3401  [SOT23]
R29  100K  [R0402]
R30  100K  [R0402]
R31  100K  [R0402]
R32  100K  [R0402]
R33  100K  [R0402]
R34  100K  [R0402]
R85  0R-0603  [R0603]
sheet PAGE09_ETH/MIC/AUDIO
C56  10uF/6.3V  [C0402_E]
C96  100nF/25V  [C0402]
C97  100nF/25V  [C0402]
C98  100nF/25V  [C0402]
C99  10uF/6.3V  [C0402_E]
C100  100nF/6.3V  [C0402]
C101  10uF/6.3V  [C0402_E]
C102  100nF/6.3V  [C0402]
C103  10uF/6.3V  [C0402_E]
C104  100nF/6.3V  [C0402]
C105  100pF/50V  [C0402]
C106  3.3nF/50V  [C0402]
C107  3.3nF/50V  [C0402]
C108  10uF/6.3V  [C0402_E]
C110  4.7uF/6.3V  [C0402]
C125  100nF/6.3V  [C0402]
C126  1nF/2KV-1206  [C1206]
C127  10uF/6.3V  [C0402_E]
C128  100nF/6.3V  [C0402]
D4  P3100SC  [SMB]
FB2  1000ohm/250mA  [FB0402]
J5  CON8 1.25mm LT  [CON8-1D25-LT]
J6  CON2 1.25mm LT  [CON2-1D25-LT]
J7  CON2 1.25mm LT  [CON2-1D25-LT]
R13  2.2R/1%  [R0402]
R19  33R  [R0402]
R28  2.2R/1%  [R0402]
R35  2.2R/1%  [R0402]
R36  2.2R/1%  [R0402]
R37  10K  [R0402]
R39  2.2R/1%  [R0402]
R40  2.2R/1%  [R0402]
R41  2.49K/1%  [R0402]
R44  10K  [R0402]
R46  10K  [R0402]
R47  0R  [R0402]
R48  1.1K  [R0402]
R49  1.1K  [R0402]
R50  10K  [R0402]
R51  1.1K  [R0402]
R52  68K/1%  [R0402]
R53  68K/1%  [R0402]
R72  2.2R/1%  [R0402]
R73  2.2R/1%  [R0402]
R74  300R  [R0402]
R75  300R  [R0402]
R76  300R  [R0402]
R77  300R  [R0402]
R81  1.1K  [R0402]
R87  10K  [R0402]
R88  10K  [R0402]
R89  10K  [R0402]
R92  10K  [R0402]
R93  75R/1%-0603  [R0603]
R94  10K  [R0402]
U8  SZ18201  [QFN32_0D5_SZ18201]
U9  FC1680C  [QFP16_1D27]
U10  CS8302M  [MSOP8_0D65]
sheet PAGE10_RST/BOOT/DEBUG
C111  1uF/6.3V  [C0402]
J8  CON4 1.0mm WT  [CON4-1D0-WT]
R55  100K  [R0402]
R56  100K  [R0402]
R57  10K  [R0402]
R58  10K  [R0402]
R59  100K  [R0402]
R60  33R  [R0402]
R61  33R  [R0402]
R62  100K  [R0402]
SW1  KEY2_SMD  [SW2_SMD]
SW2  KEY2_SMD  [SW2_SMD]

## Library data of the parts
C1 = CAP: Capacitor-22uF,+/-10%,X5R,25V-1206; Part Number: 02.0032.00; Part Type: 1206表贴普通电容; 供应商: 华新科 / Murata; 规格型号1: 1206X226K250CT / GRM31CR61E226KE15L; 联系人: 谢苏云; 手机: 15900554174; 邮箱: susan.xie@murata.com
C2 C13 C18 C19 = CAP: Capacitor-10uF,+/-20%,X5R,10V-0603; Part Number: 02.0026.00; Part Type: 0603表贴普通电容; 供应商: YAGEO / Murata; 供应商2: Murata; 规格型号1: CC0603MRX5R6BB106 / GRM188R61A106KE47D; 联系人: 谢苏云; 联系人2: 吴铭; 手机: 15900554174; 手机2: 13761466262; 邮箱: susan.xie@murata.com; 邮箱2: cherry.wu@murata.com
C3 C12 C14 C20 C62 = CAP: Capacitor-100nF,+/-10%,X7R,10V-0402; Part Number: 02.0075.00; Part Type: 0402表贴普通电容; 供应商: Murata; 供应商1: Eyang; 规格型号1: GRM155R71A104KA01D; 联系人: 谢苏云; 联系人1: 何俊; 手机: 15900554174; 手机1: 18317187178; 邮箱: susan.xie@murata.com; 邮箱1: hejunxs@szeyang.com
C4 C9 C16 = CAP: Capacitor-22pF,+/-5%,C0G,50V-0402; Part Number: 02.0008.00; Part Type: 0402表贴普通电容; 供应商: YAGEO / Murata; 供应商2: Murata; 规格型号1: CC0402JRNPO9BN220 / GRM1552C1H220JA01D; 联系人: 谢苏云; 联系人2: 吴铭; 手机: 15900554174; 手机2: 13761466262; 邮箱: susan.xie@murata.com; 邮箱2: cherry.wu@murata.com
C5 C15 C17 C21 C99 C101 C103 C127 = CAP: Capacitor-10uF,+/-20%,X5R,6.3V-0402+; Part Number: 02.0034.00; Part Type: 0402表贴普通电容; 供应商: YAGEO / Murata; 供应商2: Murata; 规格型号1: CC0402MRX5R5BB106 / GRM155R60J106ME44D; 联系人: 谢苏云; 联系人2: 吴铭; 手机: 15900554174; 手机2: 13761466262; 邮箱: susan.xie@murata.com; 邮箱2: cherry.wu@murata.com
C6 = CAP: Capacitor-10nF,+/-10%,X7R,25V-0402; Part Number: 02.0012.00; Part Type: 0402表贴普通电容; 供应商: YAGEO / Murata; 规格型号1: CC0402KRX7R8BB103 / GCM155R71E103KA37D; 联系人: 谢苏云; 手机: 15900554174; 邮箱: susan.xie@murata.com
C7 C8 = CAP: Capacitor-10uF,+/-20%,X5R,25V-0603; Part Number: 02.0027.00; Part Type: 0603表贴普通电容; 供应商: Murata; 规格型号1: GRM188R61E106MA73D; 联系人: 谢苏云; 手机: 15900554174; 邮箱: susan.xie@murata.com
C10 C23 = CAP: Capacitor-22pF,+/-5%,C0G,50V-0402; Part Number: 02.0008.00; Part Type: 0402表贴普通电容; 供应商: YAGEO / Murata; 规格型号1: CC0402JRNPO9BN220 / GRM1552C1H220JA01D; 联系人: 谢苏云; 手机: 15900554174; 邮箱: susan.xie@murata.com
C11 C95 = CAP: Capacitor-10uF,+/-20%,X5R,10V-0603; Part Number: 02.0026.00; Part Type: 0603表贴普通电容; 供应商: YAGEO / Murata; 规格型号1: CC0603MRX5R6BB106 / GRM188R61A106KE47D; 联系人: 谢苏云; 手机: 15900554174; 邮箱: susan.xie@murata.com
C22 C100 C102 C104 C128 = CAP: Capacitor-100nF,+/-10%,X7R,6.3V-0402; Part Number: 02.0075.00; Part Type: 0402表贴普通电容; 供应商: Murata; 供应商1: Eyang; 规格型号1: GRM155R70J104KA01D; 联系人: 谢苏云; 联系人1: 何俊; 手机: 15900554174; 手机1: 18317187178; 邮箱: susan.xie@murata.com; 邮箱1: hejunxs@szeyang.com
C112 C119 = CAP: Capacitor-100nF,+/-10%,X7R,10V-0402; Part Number: 02.0075.00; Part Type: 0402表贴普通电容; 供应商: Murata; 规格型号1: GRM155R71A104KA01D; 联系人: 谢苏云; 手机: 15900554174; 邮箱: susan.xie@murata.com
D1 = DIODE_WY: CHANGJIANG ELECTRONICS BZT52C12S  ZENER DIODE; Part Number: 09.0002.00; Part Type: 稳压二极管
D2 = LED_1: Part Number: 09.0003.00; Part Type: 发光二极管; 规格型号1: 0603贴片红灯; Datasheet: 0603_LED.PDF
H1-H4 = MHOLE1: MechanicalHole φ4.2mmX3.2mm Drill 3.0mmX2.0mm; Part Number: AB.0001.00; Part Type: MechanicalHole
J1 = CON_4x1: HOLY 1.25mm Pitch 4P LT SMD Connector; Part Number: 04.0005.00; Part Type: 1.25mm立贴连接器; 供应商: 深圳宏利电子; 规格型号1: 1.25mm立贴4P插座; 联系人: 谢素平; 手机: 16717558767; Datasheet: 1.25mm 立贴.pdf
L1 L3 L5 = INDUCTOR: MuRata 1285/6AS-H-2R2MS=P2 2.2uH/1.3A-2016 POWER INDUCTOR; Part Number: 03.0005.00; Part Type: 2016表贴电感; 供应商: Murata; 规格型号1: 1286AS-H-2R2MS=P2; 联系人: 谢苏云; 手机: 15900554174; 邮箱: susan.xie@murata.com; Datasheet: DFE201612C_Murata data sheet150423.pdf
L2 = INDUCTOR: MuRata DFE252012P-4R7MS=P2 4.7uH/1.4A-2520 POWER INDUCTOR; Part Number: 03.0010.00; Part Type: 2520表贴电感; 供应商: Murata; 规格型号1: DFE252012P-4R7MS=P2; 联系人: 谢苏云; 手机: 15900554174; 邮箱: susan.xie@murata.com; Datasheet: DFE252012P_Murata data sheet150828.pdf
L4 = INDUCTOR: Murata DFE201612P-1R0M=P2 1uH/2.7A（Tr=40）±20% H=1.2mm POWER INDUCTOR; Part Number: 03.0035.00; Part Type: 2016表贴电感; 供应商: Murata; 规格型号1: DFE201612P-1R0M=P2; 联系人: 谢苏云; 手机: 15900554174; 邮箱: susan.xie@murata.com; Datasheet: DFE201612P_Murata data sheet_170130.pdf
R1 R4 R5 R10 R11 R29-R34 R55 R56 R59 R62 = RES: Resistor-100K,+/-5%,1/16W-0402; Part Number: 01.0041.00; Part Type: 0402表贴普通电阻; 供应商: 厚声; 规格型号1: 0402WGJ0104TCE
R2 R7 = RES: Resistor-150K,+/-1%,1/16W-0402; Part Number: 01.0043.00; Part Type: 0402表贴高精度电阻; 供应商: 厚声; 规格型号1: 0402WGF1503TCE
R3 = RES: Resistor-33.2K,+/-1%,1/16W-0402; Part Number: 01.0032.00; Part Type: 0402表贴高精度电阻; 供应商: 厚声; 规格型号1: 0402WGF3322TCE
R6 R86 = RES: Resistor-200K,+/-1%,1/16W-0402; Part Number: 01.0045.00; Part Type: 0402表贴高精度电阻; 供应商: 厚声; 规格型号1: 0402WGF2003TCE
R8 = RES: Resistor-27K,+/-1%,1/16W-0402; Part Number: 01.0029.00; Part Type: 0402表贴高精度电阻; 供应商: 厚声; 规格型号1: 0402WGF2702TCE
R9 = RES: Resistor-120K,+/-1%,1/16W-0402; Part Number: 01.0042.00; Part Type: 0402表贴高精度电阻; 供应商: 厚声; 规格型号1: 0402WGF1203TCE
R14 R20 R27 R71 R78 = RES: Resistor-1K,+/-5%,1/16W-0402; Part Number: 01.0014.00; Part Type: 0402表贴普通电阻; 供应商: 厚声; 规格型号1: 0402WGJ0102TCE
R15 R17 R63 R98 = RES: Resistor-100K,+/-1%,1/16W-0402; Part Number: 01.0040.00; Part Type: 0402表贴高精度电阻; 供应商: 厚声; 规格型号1: 0402WGF1003TCE
R64 = RES: Resistor-300K,+/-1%,1/16W-0402; Part Number: 01.0046.00; Part Type: 0402表贴高精度电阻; 供应商: 厚声; 规格型号1: 0402WGF3003TCE
TP1-TP5 TP7-TP10 TS1 = TP: SMD Test Point φ1mm; Part Number: AA.0001.00; Part Type: Test Point
U1 U3 U4 = SY8088: 南麟 LN5058 1.5A 1.5MHz Input-2.5V~6.2V Buck Regulator; Part Number: 05.2024.00; Part Type: 降压型DCDC; 供应商: 芯晶图; 联系人: 费军; 手机: 13808850029; 邮箱: 2853085379@qq.com; Datasheet: LN5058_C.pdf
U2 = SY8120: ETA ETA8120 2A 500KHz Input-4.2V~18V Buck Regulator; Part Number: 05.2014.00; Part Type: 降压型DCDC; 供应商: ETA; 联系人: 徐卓荣; 手机: 13923780263; 邮箱: xuzhuorong@etasolution.com; Datasheet: ETA8120_V1.1.pdf
U5 = SY8088: ETA ETA3409 2A 3MHz Input-2.6V~5.5V Buck Regulator; Part Number: 05.2016.00; Part Type: 降压型DCDC; 供应商: ETA; 联系人: 徐卓荣; 手机: 13923780263; 邮箱: xuzhuorong@etasolution.com; Datasheet: ETA3409_V1.2.pdf
C24 C25 C28 C32 C43-C46 C56 C66 C108 = CAP: Capacitor-10uF,+/-20%,X5R,6.3V-0402+; Part Number: 02.0034.00; Part Type: 0402表贴普通电容; 供应商: YAGEO / Murata; 规格型号1: CC0402MRX5R5BB106 / GRM155R60J106ME44D; 联系人: 谢苏云; 手机: 15900554174; 邮箱: susan.xie@murata.com
C26 C27 C33 C35 C37 C40 C42 C47-C50 C58 C60 C61 C63-C65 C67 C68 C70 C72 C73 C75 C76 C79 C81 C83 C85-C90 C92 C94 C113 C114 C125 = CAP: Capacitor-100nF,+/-10%,X7R,6.3V-0402; Part Number: 02.0075.00; Part Type: 0402表贴普通电容; 供应商: Murata; 规格型号1: GRM155R70J104KA01D; 联系人: 谢苏云; 手机: 15900554174; 邮箱: susan.xie@murata.com
C34 C52 C53 C55 = CAP: Capacitor-10nF,+/-10%,X7R,6.3V-0402; Part Number: 02.0075.00; Part Type: 0402表贴普通电容; 供应商: Murata; 规格型号1: GRM155R70J102KA01D; 联系人: 谢苏云; 手机: 15900554174; 邮箱: susan.xie@murata.com
C41 C69 C78 C91 C93 C110 = CAP: Capacitor-4.7uF,+/-20%,X5R,6.3V-0402; Part Number: 02.0018.00; Part Type: 0402表贴普通电容; 供应商: YAGEO / Murata; 规格型号1: CC0402MRX5R5BB475 / GRM153R60J475ME15D; 联系人: 谢苏云; 手机: 15900554174; 邮箱: susan.xie@murata.com
C29-C31 C36 C38 C39 C51 C54 C57 C59 C71 C74 C84 C111 = CAP: Capacitor-1uF,+/-10%,X7R,6.3V-0402; Part Number: 02.0076.00; Part Type: 0402表贴普通电容; 供应商: Murata; 规格型号1: GRM155R70J105KA12; 联系人: 谢苏云; 手机: 15900554174; 邮箱: susan.xie@murata.com
FB1-FB10 = BEAD: Murata BLM15HG102SN1D Z=1000ohm@100MHz 250mA 1.1ohm 25%; Part Number: 03.1001.00; Part Type: 0402表贴磁珠; 供应商: Murata; 规格型号1: BLM15HG102SN1D; 联系人: 谢苏云; 手机: 15900554174; 邮箱: susan.xie@murata.com; Datasheet: BLM15HG.pdf
R16 R18 = RES: Resistor-240R,+/-1%,1/16W-0402; Part Number: 01.0010.00; Part Type: 0402表贴高精度电阻; 供应商: 厚声; 规格型号1: 0402WGF2400TCE
C80 C82 = CAP: Capacitor-12pF,+/-5%,C0G,50V-0402; ID: 8; Part Number: 02.0006.00; Part Type: 0402表贴普通电容; 供应商: YAGEO / Murata; 供应商2: Murata; 规格型号1: CC0402JRNPO9BN120 / GCM1555C1H120JA16D; 联系人: 谢苏云; 联系人2: 吴铭; 手机: 15900554174; 手机2: 13761466262; 邮箱: susan.xie@murata.com; 邮箱2: cherry.wu@murata.com
R12 = RES: Resistor-4.7R,+/-5%,1/16W-0402; Part Number: 01.0126.00; Part Type: 0402表贴普通电阻; 供应商: 厚声; 规格型号1: 0402WGJ470TCE
R21 = RES: Resistor-33R,+/-5%,1/16W-0402; ID: 18; Part Number: 01.0005.00; Part Type: 0402表贴普通电阻; 供应商: 厚声; 供应商1: Eyang; 规格型号1: 0402WGJ0330TCE; 联系人1: 何俊; 手机1: 18317187178; 邮箱1: hejunxs@szeyang.com
R22 R37 R44 R46 R50 R57 R58 R65 R68-R70 R87-R89 R92 R94 = RES: Resistor-10K,+/-5%,1/16W-0402; Part Number: 01.0023.00; Part Type: 0402表贴普通电阻; 供应商: 厚声; 规格型号1: 0402WGJ0103TCE
R23 = RES: Resistor-1M,+/-5%,1/16W-0402; ID: 49; Part Number: 01.0049.00; Part Type: 0402表贴普通电阻; 供应商: 厚声; 供应商1: Eyang; 规格型号1: 0402WGJ0105TCE; 联系人1: 何俊; 手机1: 18317187178; 邮箱1: hejunxs@szeyang.com
R19 R24 R25 R60 R61 R66 R67 = RES: Resistor-33R,+/-5%,1/16W-0402; Part Number: 01.0005.00; Part Type: 0402表贴普通电阻; 供应商: 厚声; 规格型号1: 0402WGJ0330TCE
R100 R101 = RES: Resistor-2.2R,+/-5%,1/16W-0402; Part Number: 01.0126.00; Part Type: 0402表贴普通电阻; 供应商: 厚声; 规格型号1: 0402WGJ220TCE
U6 = T41_BGA232: Ingenic T41 Smart Video Processor FBGA 232Ball 0.65mmPitch 11mmX11mm; Part Number: 06.0137.00; Part Type: CPU; 供应商: Ingenic; 规格型号1: T41
U7 = SPI_NOR: Giga Device GD25Q127CSIG 128Mbit SPI NOR FLASH MEMORY; Part Number: 06.0118.00; Part Type: SPI NOR; 供应商: 兆易创新; 联系人: 薛霆; 手机: 13910816516; 邮箱: ting.xue@gigadevice.com; Datasheet: GD25Q127C_Rev1.0.pdf
Y1 = XTAL_P4: Murata XRCGB24M000F2P01R0 Crystal initial ±20ppm 8pF; Part Number: 08.0001.00; Part Type: Crystal; 供应商: Murata; 规格型号1: XRCGB24M000F2P01R0; 联系人: 谢苏云; 手机: 15900554174; 邮箱: susan.xie@murata.com; Datasheet: XRCGB24M000F2P01R0.pdf
R26 R41 = RES: Resistor-2.49K,+/-1%,1/16W-0402; Part Number: 01.0134.00; Part Type: 0402表贴高精度电阻; 供应商: 厚声; 规格型号1: 0402WGF2491TCE
R47 R99 = RES: Resistor-0R,+/-5%,1/16W-0402; Part Number: 01.0001.00; Part Type: 0402表贴普通电阻; 供应商: 厚声; 规格型号1: 0402WGJ0000TCE
D3 D5 = ESD: Murata Vbr=7V Cj=0.5pF Bidirection ESD Protection Device; Part Number: 09.0042.00; 供应商: Murata; 联系人: 谢苏云; 手机: 15900554174; 邮箱: susan.xie@murata.com; Datasheet: ESD-LXES1UTAA1-157.pdf
D6 = ESD: WILL ESD5451X-2/TR Bidirection 17.5pF Transient Voltage Suppressor; Part Number: 09.0006.00; 供应商: Will; 规格型号1: ESD5451X-2/TR; 联系人: 安志鹏; 手机: 18321800431; 邮箱: an.zhipeng@sh-willsemi.com; Datasheet: ESD5451X.pdf
J2 = MMC_SD: TF CARD SOCKET; Part Number: 10.0003.00; Part Type: TF Card; 规格型号1: TF卡座; Datasheet: TF卡座.jpg
J3 = FPCCON_18X2: HOLY 0.5mm pitch FPC LT 36 Pin Connector; Part Number: 04.0014.00; Part Type: 0.5mm立贴FPC连接器; 供应商: 深圳宏利电子; 规格型号1: FPC0.5mm-36P立贴正位; 联系人: 谢素平; 手机: 16717558767; Datasheet: 0.5mm立式正位全包.pdf
J4 = MICROUSB_0: USB Connector  MICRO USB 带牛角有卷边无柱; Part Number: 04.0023.00; Part Type: USB连接器; 供应商: 深圳旺科达; 规格型号1: MicroB USB母座; 联系人: 童国相; 手机: 13824380089; 邮箱: wangkeda2008@163.com; Datasheet: MICRO USB 带牛角有卷边无柱.pdf
Q1 = P_MOS: WILL WPM3401 P-Channel MOSFET; Part Number: 09.0008.00; Part Type: MOS管; 供应商: Will; 联系人: 安志鹏; 手机: 18321800431; 邮箱: an.zhipeng@sh-willsemi.com; Datasheet: WPM340_datasheet.pdf
R85 = RES: Resistor-0R,+/-5%,1/10W-0603; Part Number: 01.0051.00; Part Type: 0603表贴普通电阻; 供应商: 厚声; 规格型号1: 0603WAJ0000T5E
C96-C98 = CAP: Capacitor-100nF,+/-10%,X5R,25V-0402; Part Number: 02.0038.00; Part Type: 0402表贴普通电容; 供应商: YAGEO / Murata; 规格型号1: CC0402KRX5R8BB104 / GRM155R71E104KE14D; 联系人: 谢苏云; 手机: 15900554174; 邮箱: susan.xie@murata.com
C105 = CAP: Capacitor-100pF,+/-5%,C0G,50V-0402; Part Number: 02.0059.00; Part Type: 0402表贴普通电容; 供应商: YAGEO / Murata; 规格型号1: CC0402JRNPO9BN101 / GCM1555C1H101JA16D; 联系人: 谢苏云; 手机: 15900554174; 邮箱: susan.xie@murata.com
C106 C107 = CAP: Capacitor-3.3nF,+/-10%,X7R,50V-0402; Part Number: 02.0042.00; Part Type: 0402表贴普通电容; 供应商: YAGEO / Murata; 规格型号1: CC0402KRX7R9BB332 / GRM155R71H332KA01D; 联系人: 谢苏云; 手机: 15900554174; 邮箱: susan.xie@murata.com
C126 = CAP: Capacitor-1nF,+/-10%,X7R,2KV-1206; Part Number: 02.0030.00; Part Type: 1206表贴高压电容; 供应商: YAGEO / Murata; 规格型号1: CC1206KKX7RDBB102 / GR431BR7LA102KW66L; 联系人: 谢苏云; 手机: 15900554174; 邮箱: susan.xie@murata.com
D4 = P3100: BrightKing P3100SC 防雷管 半导体放电管 10/700us_6000V; Part Number: 09.0010.00; Part Type: 防护二极管; Datasheet: P3100.pdf
J5 = CON_8x1: HOLY 1.25mm Pitch 8P LT SMD Connector; Part Number: 04.0008.00; Part Type: 1.25mm立贴连接器; 供应商: 深圳宏利电子; 规格型号1: 1.25mm立贴8P插座; 联系人: 谢素平; 手机: 16717558767; Datasheet: 1.25mm 立贴.pdf
J6 J7 = CON_2X1: HOLY 1.25mm Pitch 2P LT SMD Connector; Part Number: 04.0001.00; Part Type: 1.25mm立贴连接器; 供应商: 深圳宏利电子; 规格型号1: 1.25mm立贴2P插座; 联系人: 谢素平; 手机: 16717558767; Datasheet: 1.25mm 立贴.pdf
R13 R28 R35 R36 R39 R40 R72 R73 = RES: Resistor-2.2R,+/-1%,1/16W-0402; Part Number: 01.0126.00; Part Type: 0402表贴高精度电阻; 供应商: 厚声; 规格型号1: 0402WGF220KTCE
R48 R49 R51 R81 = RES: Resistor-1.1K,+/-5%,1/16W-0402; Part Number: 01.0149.00; Part Type: 0402表贴普通电阻; 供应商: 厚声; 规格型号1: 0402WGJ0112TCE
R52 R53 = RES: Resistor-68K,+/-1%,1/16W-0402; Part Number: 01.0038.00; Part Type: 0402表贴高精度电阻; 供应商: 厚声; 规格型号1: 0402WGF6802TCE
R74-R77 = RES: Resistor-300R,+/-5%,1/16W-0402; Part Number: 01.0011.00; Part Type: 0402表贴普通电阻; 供应商: 厚声; 规格型号1: 0402WGJ0301TCE
R93 = RES: Resistor-75R,+/-1%,1/10W-0603; Part Number: 01.0052.00; Part Type: 0603表贴高精度电阻; 供应商: 厚声; 规格型号1: 0603WAF750JT5E
U8 = SZ18201: Motor Comm SZ18201 Single Chip 10/100M Ethernet Phyceiver with Auto MDIX; Part Number: 06.0123.00; Part Type: ETH Phy 芯片; 供应商: Motor Comm; Datasheet: SZ18201_2021-05-28.PDF
U9 = FC1680C: IC-FLY FC1680C 10/100 Small Package Transformer module; Part Number: 06.0010.00; Part Type: 网络变压器; 供应商: 上海飞芯电子; 联系人: 刘经纬; 手机: 18621560356; Datasheet: FC1680C.20120213.pdf
U10 = CS8302: 上海智浦欣 CS8302M 3W 单声道 超低EMI 无滤波器 D类音频功放; Part Number: 06.0105.00; Part Type: 功放芯片; 供应商: 芯晶图电子; 联系人: 费军; 手机: 13808850029; 邮箱: eric.fei@shinychip.com; Datasheet: CS8302M_ch_v1.0.pdf
J8 = CON_4X1: HOLY 1.0mm Pitch 4P WT SMD Connector; Part Number: 04.0004.00; Part Type: 1.0mm卧贴连接器; 供应商: 深圳宏利电子; 规格型号1: 1mm卧贴4P插座; 联系人: 谢素平; 手机: 16717558767; Datasheet: 1.0mmA 卧贴.pdf
SW1 SW2 = PUSHBUTTON: PUSHBUTTON 3mmX6mm 2Pin; Part Number: 04.1001.00; Part Type: 按键; 供应商: 深圳旺科达; 规格型号1: TS-020A/4.3A; 联系人: 童国相; 手机: 13824380089; 邮箱: wangkeda2008@163.com

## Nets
AVDD33: C127.1 C128.1 FB2.1 U8.7(AVDD33_1)
AVDDL_REG: C59.1 C60.1 U6.R16(AVDDL_REG)
DVDD1V2OUT: C57.1 C58.1 U6.T14(DVDD1V2OUT)
GND: C1.2 C2.2 C3.2 C5.2 C7.2 C8.2 C11.2 C12.2 C13.2 C14.2 C15.2 C17.2 C18.2 C19.2 C20.2 C21.2 C22.2 C24.2 C25.2 C26.2 C27.2 C28.2 C29.2 C30.2 C31.2 C32.2 C33.2 C34.2 C35.2 C36.2 C37.2 C38.2 C39.2 C41.2 C42.1 C43.2 C44.2 C45.2 C46.2 C47.2 C48.2 C49.2 C50.2 C51.2 C52.2 C53.2 C54.2 C55.2 C57.2 C58.2 C59.2 C60.2 C61.1 C62.2 C63.2 C64.2 C65.2 C66.2 C69.2 C70.2 C71.2 C72.2 C73.2 C74.2 C75.2 C76.2 C78.2 C79.2 C80.1 C81.1 C82.1 C83.2 C84.2 C85.2 C86.2 C87.2 C88.2 C89.2 C90.2 C91.2 C93.2 C94.2 C95.2 C96.1 C97.1 C98.1 C99.2 C100.2 C101.2 C102.2 C103.2 C104.2 C106.2 C108.2 C110.2 C111.2 C112.2 C113.2 C114.2 C119.2 C125.2 C126.1 C127.2 C128.2 D1.1 D3.1(ANODE) D4.2 D5.1(ANODE) D6.1(ANODE) H1.1(A) H2.1(A) H3.1(A) H4.1(A) J1.3 J1.5(S1) J1.6(S2) J2.6(VSS2) J2.10(GND_2) J2.11(GND_1) J2.12(PAD1) J2.13(PAD2) J3.7 J3.10 J3.15 J3.20 J3.27 J3.29 J3.37(S1) J3.38(S2) J4.5(GND1) J4.6(GND2) J4.7(GND3) J4.8(GND4) J4.9(GND5) J4.10(GND6) J4.11(GND7) J5.7 J5.9(S1) J5.10(S2) J6.3(S1) J6.4(S2) J7.3(S1) J7.4(S2) J8.2 J8.5(S1) J8.6(S2) R3.1 R8.1 R9.1 R14.2 R16.2 R17.1 R18.2 R21.1 R26.2 R27.1 R41.2 R46.1 R47.1 R49.1 R50.2 R59.1 R64.2 R71.1 R78.1 R88.1 R89.1 R92.1 R98.1 SW1.1 SW2.1 U1.2(GND) U2.2(GND) U3.2(GND) U4.2(GND) U5.2(GND) U6.C9(DDRPLL_VSSA) U6.G5(PLL_AVSS) U6.G6(VSS1) U6.G7(VSS2) U6.G8(VSS3) U6.G9(VSS4) U6.G10(VSS5) U6.G11(VSS6) U6.G12(VSS7) U6.G13(VSS8) U6.J6(VSS9) U6.J7(VSS10) U6.J8(VSS11) U6.J9(VSS12) U6.J10(VSS13) U6.J11(VSS14) U6.J12(VSS15) U6.K6(VSS16) U6.K7(VSS17) U6.K8(VSS18) U6.K9(VSS19) U6.K10(VSS20) U6.K11(VSS21) U6.K12(VSS22) U6.L6(VSS23) U6.L7(VSS24) U6.L8(VSS25) U6.L9(VSS26) U6.L10(VSS27) U6.L11(VSS28) U6.L12(VSS29) U6.M7(VSS30) U6.M8(VSS31) U6.M9(VSS32) U6.M10(VSS33) U6.M11(VSS34) U6.M12(VSS35) U6.M13(VSS36) U6.N5(CSI_VSSA) U6.N12(VSS37) U6.N13(SADC_AGND) U6.N15(SADC_VIN3) U6.P4(CODEC_AVSS) U6.P16(SADC_VIN2) U6.R17(SADC_VIN1) U7.4(GND) U8.33(GND) U10.7(GND) Y1.2 Y1.4
VBUS: TP10.1 U6.U3(VBUS)
VCC_0V8: C21.1 C22.1 C23.2 C43.1 C44.1 C45.1 C46.1 C47.1 C48.1 C49.1 C50.1 C52.1 C53.1 C55.1 C113.1 FB4.1 FB8.2 L4.2 R63.2 TS1.1 U6.H5(VDD1) U6.H6(VDD2) U6.H7(VDD3) U6.H8(VDD4) U6.H9(VDD5) U6.H10(VDD6) U6.H11(VDD7) U6.H12(VDD8) U6.H13(VDD9) U6.J5(VDD10) U6.J13(VDD11) U6.K5(VDD12) U6.K13(VDD13) U6.L5(VDD14) U6.L15(VDD_RTC) U6.M5(VDD15) U6.M6(VDD16) U6.N6(VDD17) U6.N7(VDD18) U6.N8(VDD19) U6.N9(VDD20) U6.N10(VDD21)
VCC_1V8: C16.1 C17.1 C31.1 C83.1 C87.1 C88.1 C114.1 FB1.2 FB3.2 FB5.1 FB7.1 FB9.2 FB10.1 L5.2 R20.1 R62.1 R86.2 TP5.1 U6.C4(VDDIO2) U6.K2(VDDIO18_2) U6.L17(VDDIO_RTC) U6.N11(VDDIO18_1)
VCC_3V3: C4.1 C5.1 C39.1 C51.1 C81.2 C89.1 C90.1 C91.1 C92.1 C99.1 C100.1 D2.1(ANODE) FB2.2 FB6.1 J3.1 J3.2 J8.1 L1.2 Q1.2(SOURCE) R2.2 R22.2 R34.1 R37.1 R44.1 R55.2 R56.2 R57.1 R58.1 R65.2 R68.2 R69.2 R70.2 R87.1 R94.2 TP1.1 U6.J14(VDDIO1_2) U6.P9(VDDIO1_1) U7.8(VCC) U8.14(DVDD33_1)
VCC_5V: C2.1 C10.1 C11.1 C12.1 C13.1 C18.1 C19.1 C20.1 C108.1 J3.34 J3.35 J3.36 L2.2 R1.1 R5.1 R6.1 R10.1 R11.1 R85.2 TP4.1 U1.4(IN) U3.4(IN) U4.4(IN) U5.4(IN) U10.6(VDD)
VCC_12V: C1.1 C7.1 C8.1 D1.2 J1.4 R4.1 TP2.1 U2.5(VIN)
VCC_DDR: C9.1 C15.1 C24.1 C25.1 C26.1 C27.1 C28.1 C32.1 C33.1 C34.1 C35.1 C37.1 C40.2 C41.1 L3.2 R7.2 R15.2 TP3.1 U6.E6(VDDMEM1) U6.E7(VDDMEM2) U6.E8(VDDMEM3) U6.E9(VDDMEM4) U6.E10(VDDMEM5) U6.E11(VDDMEM6) U6.E12(VDDMEM7) U6.F5(DDRVDD1) U6.F6(DDRVDD2) U6.F7(DDRVDD3) U6.F8(DDRVDD4) U6.F9(DDRVDD5) U6.F10(DDRVDD6) U6.F11(DDRVDD7) U6.F12(DDRVDD8)
VDDMSC0: C93.1 C94.1 J2.4(VDD) Q1.3(DRAIN) R29.1 R30.1 R31.1 R32.1 R33.1
ACTA: J5.6 R74.2 R77.1
ADC_AVDD: C38.1 C76.1 FB10.2 U6.N16(SADC_VREFP) U6.N17(SADC_AVDD)
BOOTSEL0: R55.1 SW1.2 U6.A9(BOOT_SEL0_PC00)
BOOTSEL1: R56.1 R59.2 U6.B9(BOOT_SEL1_PC01)
CIM_MCLK: J3.28 R67.1
CLK_CTL: R92.2 U8.12(RXD[3]/CLK_CTL)
CORE_FB: C23.1 R63.1 R64.1 U5.5(FB)
CSI_VCC08: C84.1 C85.1 FB8.1 U6.N2(CSI_VCCA08)
CSI_VCC18: C29.1 C86.1 FB9.1 U6.K3(CSI_VCCA18)
DDR_VREF: C40.1 C42.2 R15.1 R17.2 U6.E5(DDR_VREF)
DDRPLL: C54.1 C64.1 FB1.1 U6.B8(DDRPLL_VCCA)
DVP_D0: J3.11 U6.L2(CSI_DATAN0_DVP_D0)
DVP_D1: J3.12 U6.L1(CSI_DATAP0_DVP_D1)
DVP_D2: J3.13 U6.N1(CSI_DATAN1_DVP_D2)
DVP_D3: J3.14 U6.M3(CSI_DATAP1_DVP_D3)
DVP_D4: J3.16 U6.M2(CSI_CLKN_DVP_D4)
DVP_D5: J3.17 U6.L3(CSI_CLKP_DVP_D5)
DVP_D6: J3.18 U6.H2(SD0_DVP_D6_PA06)
DVP_D7: J3.19 U6.H3(SD1_DVP_D7_PA07)
DVP_D8: J3.21 U6.G1(SD2_DVP_D8_PA08)
DVP_D9: J3.22 U6.G2(SD3_DVP_D9_PA09)
DVP_HSYNC: J3.8 U6.J2(CS2_DVP_HSYNC_PA16)
DVP_PCLK: J3.26 U6.F3(SA0_DVP_PCLK__PA14)
DVP_PWDN: J3.30 U6.E2(WAIT_PA19)
DVP_RST: J3.33 U6.E3(SA2_PA18)
DVP_VSYNC: J3.9 U6.J3(RD_DVP_VSYNC_PA17)
EN_DLDO: R27.2 R69.1 U6.U15(EN_DLDO)
EXCLKI: C80.2 R23.2 U6.C1(EXCLK_XIN) Y1.1
EXCLKO: R23.1 R24.2 U6.D2(EXCLK_XOUT)
GMAC_MDCK: U6.R10(GMAC_MDCK_SMB2_SDA_PB10) U8.22(MDC)
GMAC_MDIO: R37.2 U6.T10(GMAC_MDIO_SMB2_SCK_PB11) U8.23(MDIO)
GMAC_PHY_CLK: R66.1 U8.31(XTAL_IN)
GMAC_RST_N: C125.1 R70.1 R99.2 U6.A11(DMIC_CLK_SMB2_SCK_PB28) U8.21(RESET_N)
GMAC_RXD0: U6.U13(GMAC_RXD0_PWM6_PB15) U8.9(RXD[0])
GMAC_RXD1: R44.2 U6.R12(GMAC_RXD1_PWM7_PB16) U8.10(RXD[1])
GMAC_RXDV: U6.U9(GMAC_RXDV_PWM3_PB09) U8.26(CRS/CRS_DV)
GMAC_TXCLK: R19.1 U6.T12(GMAC_TXCLK_PB06)
GMAC_TXD0: U6.R11(GMAC_TXD0_PWM4_PB13) U8.16(TXD[0])
GMAC_TXD1: U6.T11(GMAC_TXD1_PWM5_PB14) U8.17(TXD[1])
GMAC_TXEN: U6.U11(GMAC_TXEN_PWM2_PB08) U8.20(TXEN)
HPOUTL: C107.2 U6.T1(HPOUTL)
I2C0_SCK: J3.3 U6.J4(SD7_SMB0_SCK_PA13)
I2C0_SDA: J3.6 U6.J1(SD6_SMB0_SDA_PA12)
IR: J3.25 U6.B12(DMIC_DAT0_UART4_TXD_PB29)
IRCUTN: J3.31 U6.E17(MSC1_D1_PB18)
IRCUTP: J3.32 U6.E16(MSC1_D0_PB17)
LINKA: J5.8 R75.2 R76.1
MCLK: R67.2 U6.E1(SA1_DVP_MCLK_PA15)
MDI_RN: R40.2 R73.2 U9.1(TD+/RD+)
MDI_RP: R39.2 R72.2 U9.3(TD-/RD-)
MDI_TN: R28.2 R36.2 U9.6(RD+/TD+)
MDI_TP: R13.2 R35.2 U9.8(RD-/TD-)
MICBIAS: C78.1 C79.1 C110.1 R81.1 U6.P3(MICBIAS)
MICNL: C68.2 C105.1 J6.1 R48.1
MICPL: C67.2 C105.2 J6.2 R51.2
MSC0_CLK_PB04: J2.5(CLK) R25.1
MSC0_CMD_PB05: J2.3(CMD) R30.2 U6.G17(MSC0_CMD_PB05)
MSC0_D0_PB00: J2.7(DAT0) R29.2 U6.H16(MSC0_D0_PB00)
MSC0_D1_PB01: J2.8(DAT1) R31.2 U6.J15(MSC0_D1_PB01)
MSC0_D2_PB02: J2.1(DAT2) R32.2 U6.G15(MSC0_D2_PB02)
MSC0_D3_PB03: J2.2(DAT3) R33.2 U6.G16(MSC0_D3_PB03)
PHY_LED0: R74.1 U6.R13(LED0)
PHY_LED1: R75.1 U6.R15(LED1)
PHY_RST_N: C61.2 R99.1 U6.T13(PHY_RST)
PHYLED0: R77.2 R88.2 U8.24(LED0/PHYAD[0])
PHYLED1: R76.2 R89.2 U8.25(LED1/PHYAD[1])
PLL_AVDD: C30.1 C63.1 FB3.1 U6.D3(PLL_AVDD)
POR_CTRL: R20.2 R78.2 U6.K16(POR_CTL)
PPRST_: C111.1 R62.2 SW2.2 U6.L16(PPRST_)
RD_N: R73.1 U6.U17(RD_N)
RD_P: R72.1 U6.T17(RD_P)
RST_OUT: TP8.1 U6.J16(RST_OUT)
RX+: J5.3 U9.14(TX-/RX-)
RX-: J5.4 U9.16(TX+/RX+)
RX_DV: R68.1 U6.P14(RX_DV)
RXD3: R65.1 R71.2 U6.R14(RXD3)
RXDV: R87.2 U8.8(RXDV)
SD0_CD_N: C92.2 J2.9(CD) Q1.1(GATE) R34.2 U6.B11(DRV_VBUS_SMB2_SDA_PB27)
SFC_CS_N: R22.1 U6.T4(SFC0_CE_PA28) U7.1(~{CS})
SFC_SCLK: U6.R6(SFC0_CLK_PA27) U7.6(SCLK)
SFC_SIO0: U6.U5(SFC0_DT_IO0_PA23) U7.5(SI/SIO0)
SFC_SIO1: U6.R5(SFC0_DR_IO1_PA24) U7.2(SO/SIO1)
SFC_SIO2: U6.T5(SFC0_WP_IO2_PA26) U7.3(~{WP}/SIO2)
SFC_SIO3: U6.T6(SFC0_HOLD_IO3_PA25) U7.7(~{RESET}/SIO3)
SPEAK_EN: R50.1 U6.B10(GPIO_PB31) U10.1(/SD)
TD_N: R28.1 U6.U16(TD_N)
TD_P: R13.1 U6.T16(TD_P)
TRXN0: R36.1 U8.4(TRXN0)
TRXN1: R40.1 U8.6(TRXN1)
TRXP0: R35.1 U8.3(TRXP0)
TRXP1: R39.1 U8.5(TRXP1)
TX+: J5.1 U9.9(RX-/TX-)
TX-: J5.2 U9.11(RX+/TX+)
UART1_RX: R61.2 U6.F16(UART1_RXD_PB24)
UART1_RXD: J8.3 R57.2 R61.1
UART1_TX: R60.2 U6.F15(UART1_TXD_PB23)
UART1_TXD: J8.4 R58.2 R60.1
USB0PN: D5.2(CATHODE) J4.2(D-) R100.2
USB0PP: D3.2(CATHODE) J4.3(D+) R101.2
USB_AVD08: C71.1 C72.1 FB4.2 U6.R4(USB_AVD08)
USB_AVD18: C36.1 C73.1 FB5.2 U6.T3(USB_AVD18)
USB_AVD33: C74.1 C75.1 FB6.2 U6.R3(USB_AVD33)
USBID: TP7.1 U6.U2(USB0ID)
N16515966: C10.2 R6.2 R8.2 U2.3(FB)
N16516036: R4.2 U2.4(EN)
N16516040: C6.1 U2.1(BS)
N16516056: C6.2 L2.1 U2.6(LX)
N16516370: C3.1 R1.2 U1.1(EN)
N16516568: C4.2 R2.1 R3.2 U1.5(FB)
N16516600: L1.1 U1.3(LX)
N16516732: D2.2(CATHODE) R14.1
N16520392: C95.1 C119.1 D6.2(CATHODE) J4.1(VBUS) R85.1
N16524050: J7.2 U10.5(VO+)
N16524058: J7.1 U10.8(VO-)
N16524110: R53.1 U10.4(-IN)
N16524120: C107.1 R53.2
N16524124: C106.1 R52.2
N16524196: R52.1 U10.3(+IN)
N16524342: C56.2 R51.1 R81.2
N16524476: C56.1 R48.2 R49.2
N16557488: C82.2 R24.1 Y1.3
N16609473: R16.1 U6.F13(DDR_ZQ)
N16609477: R18.1 U6.D9(RZQ)
N16629326: R46.2 U8.28(RXER)
N16629374: R47.2 U8.32(XTAL_OUT)
N16629796: R41.1 U8.1(PBIAS)
N16629982: C103.1 C104.1 U8.29(DVDDL_REG)
N16630018: C101.1 C102.1 U8.2(AVDDL_REG)
N16630046: R94.1 U8.30(NC)
N16630124: C98.2 U9.7(CT2)
N16630144: D4.1 R93.2 U9.10(CT3) U9.13(MCT) U9.15(CT4)
N16630182: C97.2 U9.5(CT)
N16630194: C96.2 U9.2(CT1)
N16630328: C126.2 R93.1
N16679971: R21.2 U6.D4(EFUSE_AVDD)
N16680187: C65.1 C66.1 FB7.2 U6.R1(CODEC_AVDD)
N16680357: C69.1 C70.1 U6.R2(VCM)
N16685513: R66.2 U6.T9(GMAC_PHY_CLK_PB07)
N16707574: R101.1 U6.T2(USB0PP)
N16707578: R100.1 U6.U1(USB0PN)
N16707590: C68.1 U6.P2(MICNL)
N16710875: R25.2 U6.H15(MSC0_CLK_PB04)
N16712105: C67.1 U6.N3(MICPL)
N16792128: R26.1 U6.T15(RBIAS)
N16932770: C62.1 R11.2 U4.1(EN)
N16932828: L5.1 U4.3(LX)
N16932830: C16.2 R86.1 R98.2 U4.5(FB)
N16959210: C14.1 R5.2 U3.1(EN)
N16959271: C9.2 R7.1 R9.2 U3.5(FB)
N16959277: L3.1 U3.3(LX)
N16959996: C112.1 R10.2 U5.1(EN)
N16960077: L4.1 U5.3(LX)
N16967238: R19.2 U8.15(TXC)
N17033099: R12.1 U6.P15(SADC_VIN0)
N17033102: R12.2 TP9.1

Not connected (* = marked no-connect by the designer): J1 1* 2*; J3 4* 5* 23* 24*; J4 4(ID)*; J5 5*; U6 A1(MSC1_CLK_PC02)* A2(MSC1_D1_PC05)* A3(SSI_SLV_CE0_I2S_DAC_LRCK_PC16)* A5(I2S_ADC_MCLK_PC12)* A7(SMB1_SDA_PC19)* A13(SLCD_TE_PWM4_PD09)* A15(SLCD_D0_UART3_TXD_PD00)* A16(SLCD_D2_UART4_TXD_PD02)* A17(SLCD_D4_UART5_TXD_PD04)* B1(MSC1_D3_PC07)* B2(MSC1_D0_PC04)* B3(SSI_SLV_DT_I2S_SDTO_PC17)* B4(SSI_SLV_CLK_I2S_DAC_BCLK_PC15)* B5(SSI_SLV_DR_I2S_SDTI_PC18)* B6(SMB2_SDA_PC08)* B7(I2S_ADC_BCLK_PC13)* B13(SLCD_CS_PWM5_PD10)* B14(SLCD_WR_PD08)* B15(SLCD_D1_UART3_RXD_PD01)* B16(SLCD_D5_UART5_RXD_PD05)* B17(SLCD_D6_SMB1_SDA_PD06)* C2(MSC1_D2_PC06)* C3(MSC1_CMD_PC03)* C5(I2S_DAC_MCLK_PC11)* C6(SMB2_SCK_PC09)* C7(I2S_ADC_LRCK_PC14)* C8(SMB1_SCK_PC20)* C10(SMB1_SCK_UART3_RXD_PB26)* C11(SMB1_SDA_UART3_TXD_PB25)* C12(DMIC_DAT1_UART4_RXD_PB30)* C13(SLCD_DC_PWM6_PD11)* C14(SLCD_RDY_PWM7_PD12)* C15(SLCD_D3_UART4_RXD_PD03)* C16(SLCD_D7_SMB1_SCK_PD07)* C17(MSC1_D2_TMS_PB21)* D14(TRST_)* D15(MSC1_D3_PB22)* D16(MSC1_CMD_PB19)* E15(MSC1_CLK_TCK_PB20)* F2(NC_2)* G3(NC_1)* J17(WKUP_PD31)* K15(PWRON)* L13(TEST_TE)* M15(OSC32_XO)* M16(OSC32_XI)* R7(SFC1_CE_PA29)* R8(SFC1_DT_IO0_PA20)* R9(SFC1_HOLD_IO3_PA31)* T7(SFC1_DR_IO1_PA21)* T8(SFC1_CLK_PA22)* U7(SFC1_WP_IO2_PA30)*; U8 11(RXD[2]/INT_N)* 13(RXC)* 18(TXD[2])* 19(TXD[3])* 27(COL)*; U9 4(NC1)* 12(NC2)*; U10 2(NC)*

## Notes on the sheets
sheet 1
- RD_T41_TOMCAT_D
- INGENIC
- Schematic Revision  1.1
- Title
- Page
- COVER SHEET
- 1
- SYSTEM ARCHITECTURE
- 2
- POWER_SUPPLY
- 3
- T41_POWER
- 4
- T41_INTERFACE1
- 5
- T41_INTERFACE2
- 6
- T41_INTERFACE3
- 7
- DVP/SD_CARD/USB
- 8
- ETH/MIC/AUDIO
- 9
- RST/BOOT/DEBUG
- 10
- REVISION HISTORY
- 11
sheet 2
- SYSTEM_ARCHITECT
- USB2.0
- USB
  HOST
- MIC
- RMII
- ETHERNET CONTROLLER
- HEADER
- SPK
- SFC
- SPI FLASH(SPI)
- T41-BGA232
- MSC0
- UART1
- SD SOCKET
- DEBUG
- TP
- ADC
- GPIO
- CAMERA
  HEADER
- DVP I2C
- 24M
- Reset
- CRY
- Reset
- VCC_0V8
- 2A Max
- DCDC
- DC_12V_IN
- DCDC
- VCC_5V
- DCDC
- VCC_DDR
- 1A Max
- 2A Max
- VCC_3V3
- 1A Max
- DCDC
- VCC_1V8
- 1A Max
- DCDC
sheet 3
- POWER_SUPPLY
- 12V_DC_IN
- 3.3V/1A
- 0.6V
- Note: Compatible with ETA3486
- VOUT=(1+150K/33.2K)*0.6=3.3V
- 5V/2A
- VCC_DDR/1A
- 0.6V
- 0.6V
- Note: Compatible with ETA3486
- VCC_DDR=(1+200K/100K)*0.6=1.8V for DDR2
- Note: Compatible with LN3496
- VCC_DDR=(1+150K/100K)*0.6=1.5V for DDR2L or DDR3
- VOUT=(1+200K/27K)*0.6=5.0V
- VCC_DDR=(1+150K/120K)*0.6=1.35V for DDR3L
- √
- 1.8V/1A
- VDD Core 0.8V/2A
- 0.6V
- 0.6V
- Note: Compatible with ETA3486
- VCC_1V8=(1+200K/100K)*0.6=1.8V
- VOUT=(1+100K/300K)*0.6=0.8V
- LED
- Mechanical Hole
sheet 4
- T41_POWER
sheet 5
- T41_INTERFACE1
- NOTE：
  Concatenated a 2.2 ohm resistor on usb bus for
  prevent surge and ESD event
- NC
- POR CTRL
- 1    POR
- 0    PPRST
- NOR FLASH
- CLK
- NC
sheet 6
- T41_INTERFACE2
- NC
- NC
- NC
sheet 7
- T41_INTERFACE3
sheet 8
- Date
- Revision
- Change
- Sep 20 2022
- Rev1.0
- 1. First Revision
- Nov 01 2022
- Rev1.1
- 1.T41.G3&F2 Ball  Change to NC.
- 2.ADC Channel Series 4.7R Resistor.
- 3.Update T41 package
sheet 9
- ETH_RMII_MIC_AUDIO
- ETH RMII
- NC
- NC
- NC
- NC
- Note: R94 Compatiable with JL1101
- NC
- RXD1:
  Internal Pulled low,defaut
  0:LED Mode
  1:WOL Mode
- NC
- NC
- RX_DV:
  Internal Pulled low,defaut
  0:MII Mode
  1:RMII Mode
- NC
- NC
- CLK_CTL:
  Internal Pulled low,defaut
  0:REF_CLK output
  1:REF_CLK intput
- NC
- PHY Address:00000b
- MIC
- AUDIO
- NC
- -
- +
sheet 10
- RST_BOOT_DEBUG
- DEBUG
- BOOT
- NC
- BOOT_SEL1
- BOOT_SEL0
- MMC/SD boot@MSC0(MMC/SD use GPIO Port B.
  MSC1 use GPIO Port C)
- BOOT FROM
- 0
- 0
- 1
- 0
- UART boot @ CS2(Ymodem@115200/9600)
- 1
- 1
- 0
- 1
- SFC boot @ CS4(SPI boot)
- USB boot @USB2.0 device, EXTCLK=24MHz
- RESET CIRCUITS
- NC
- NC
sheet 11
- DVP_SD_CARD_USB
- SD CARD
- DVP
- USB2.0
- NC
